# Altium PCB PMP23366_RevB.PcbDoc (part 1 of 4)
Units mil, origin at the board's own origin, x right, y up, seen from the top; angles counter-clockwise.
Board outline 6500 x 4250 mil, 4 copper layers (Top Layer 1, Inner Layer 2, Inner Layer 3, Bottom Layer 1), stack 75.824 mil thick; 370 components, 218 nets, 1221 pads, 351 vias.
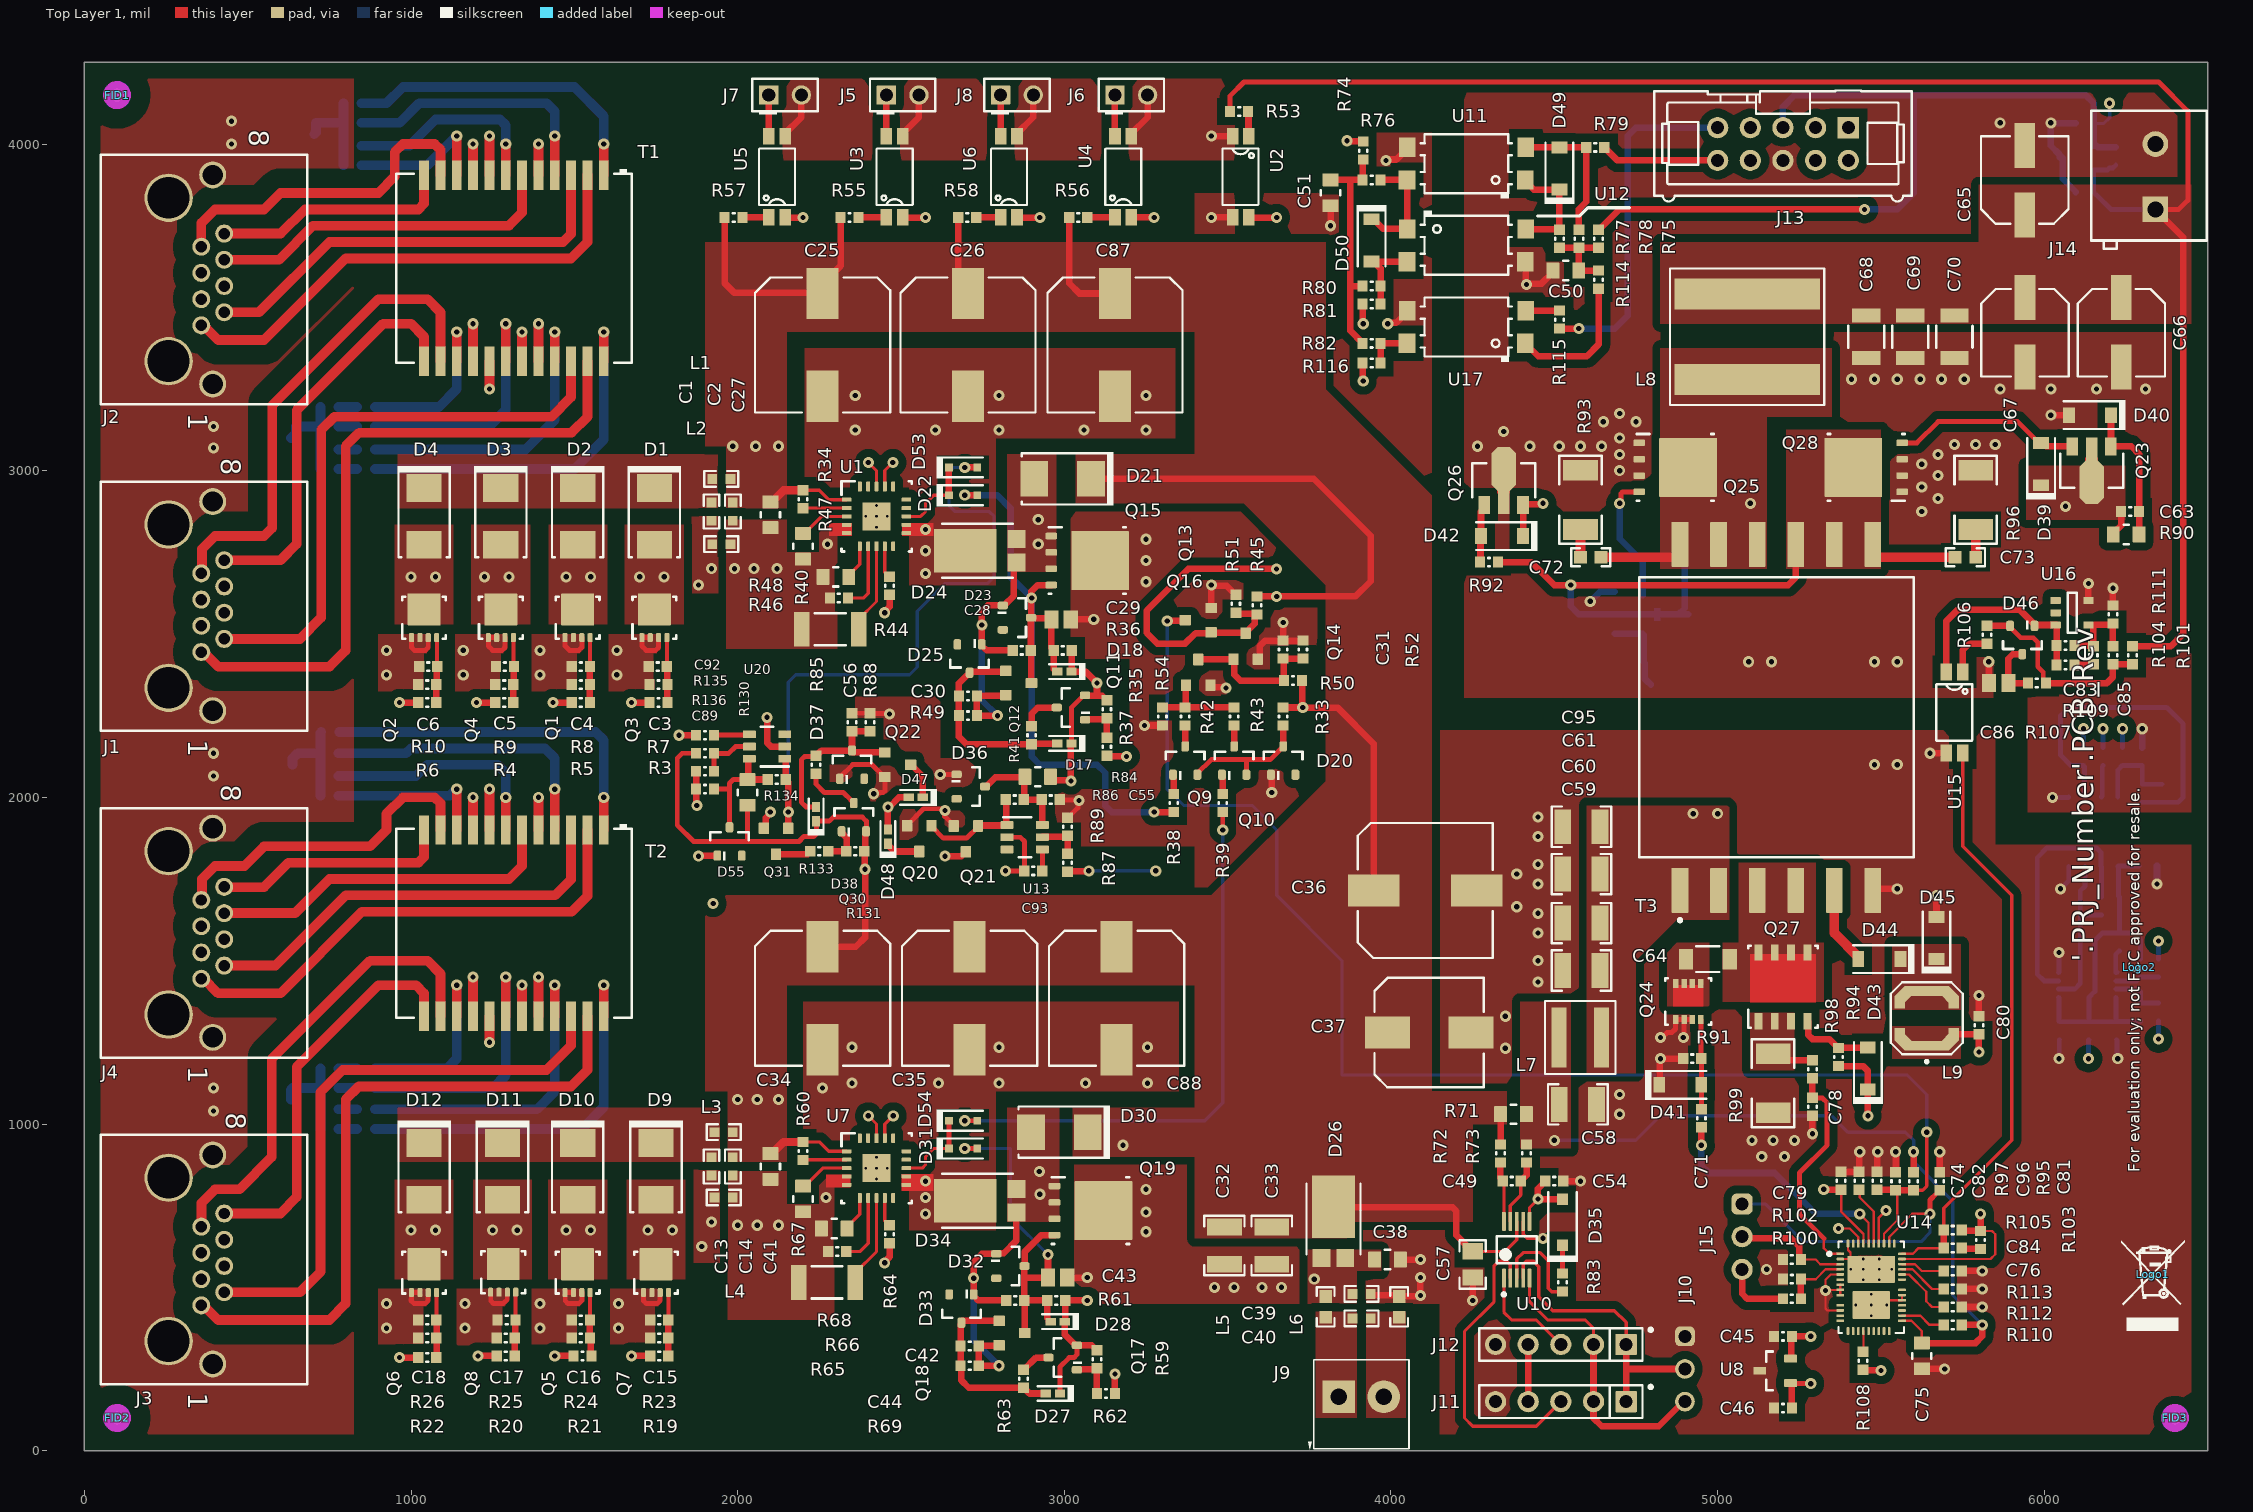
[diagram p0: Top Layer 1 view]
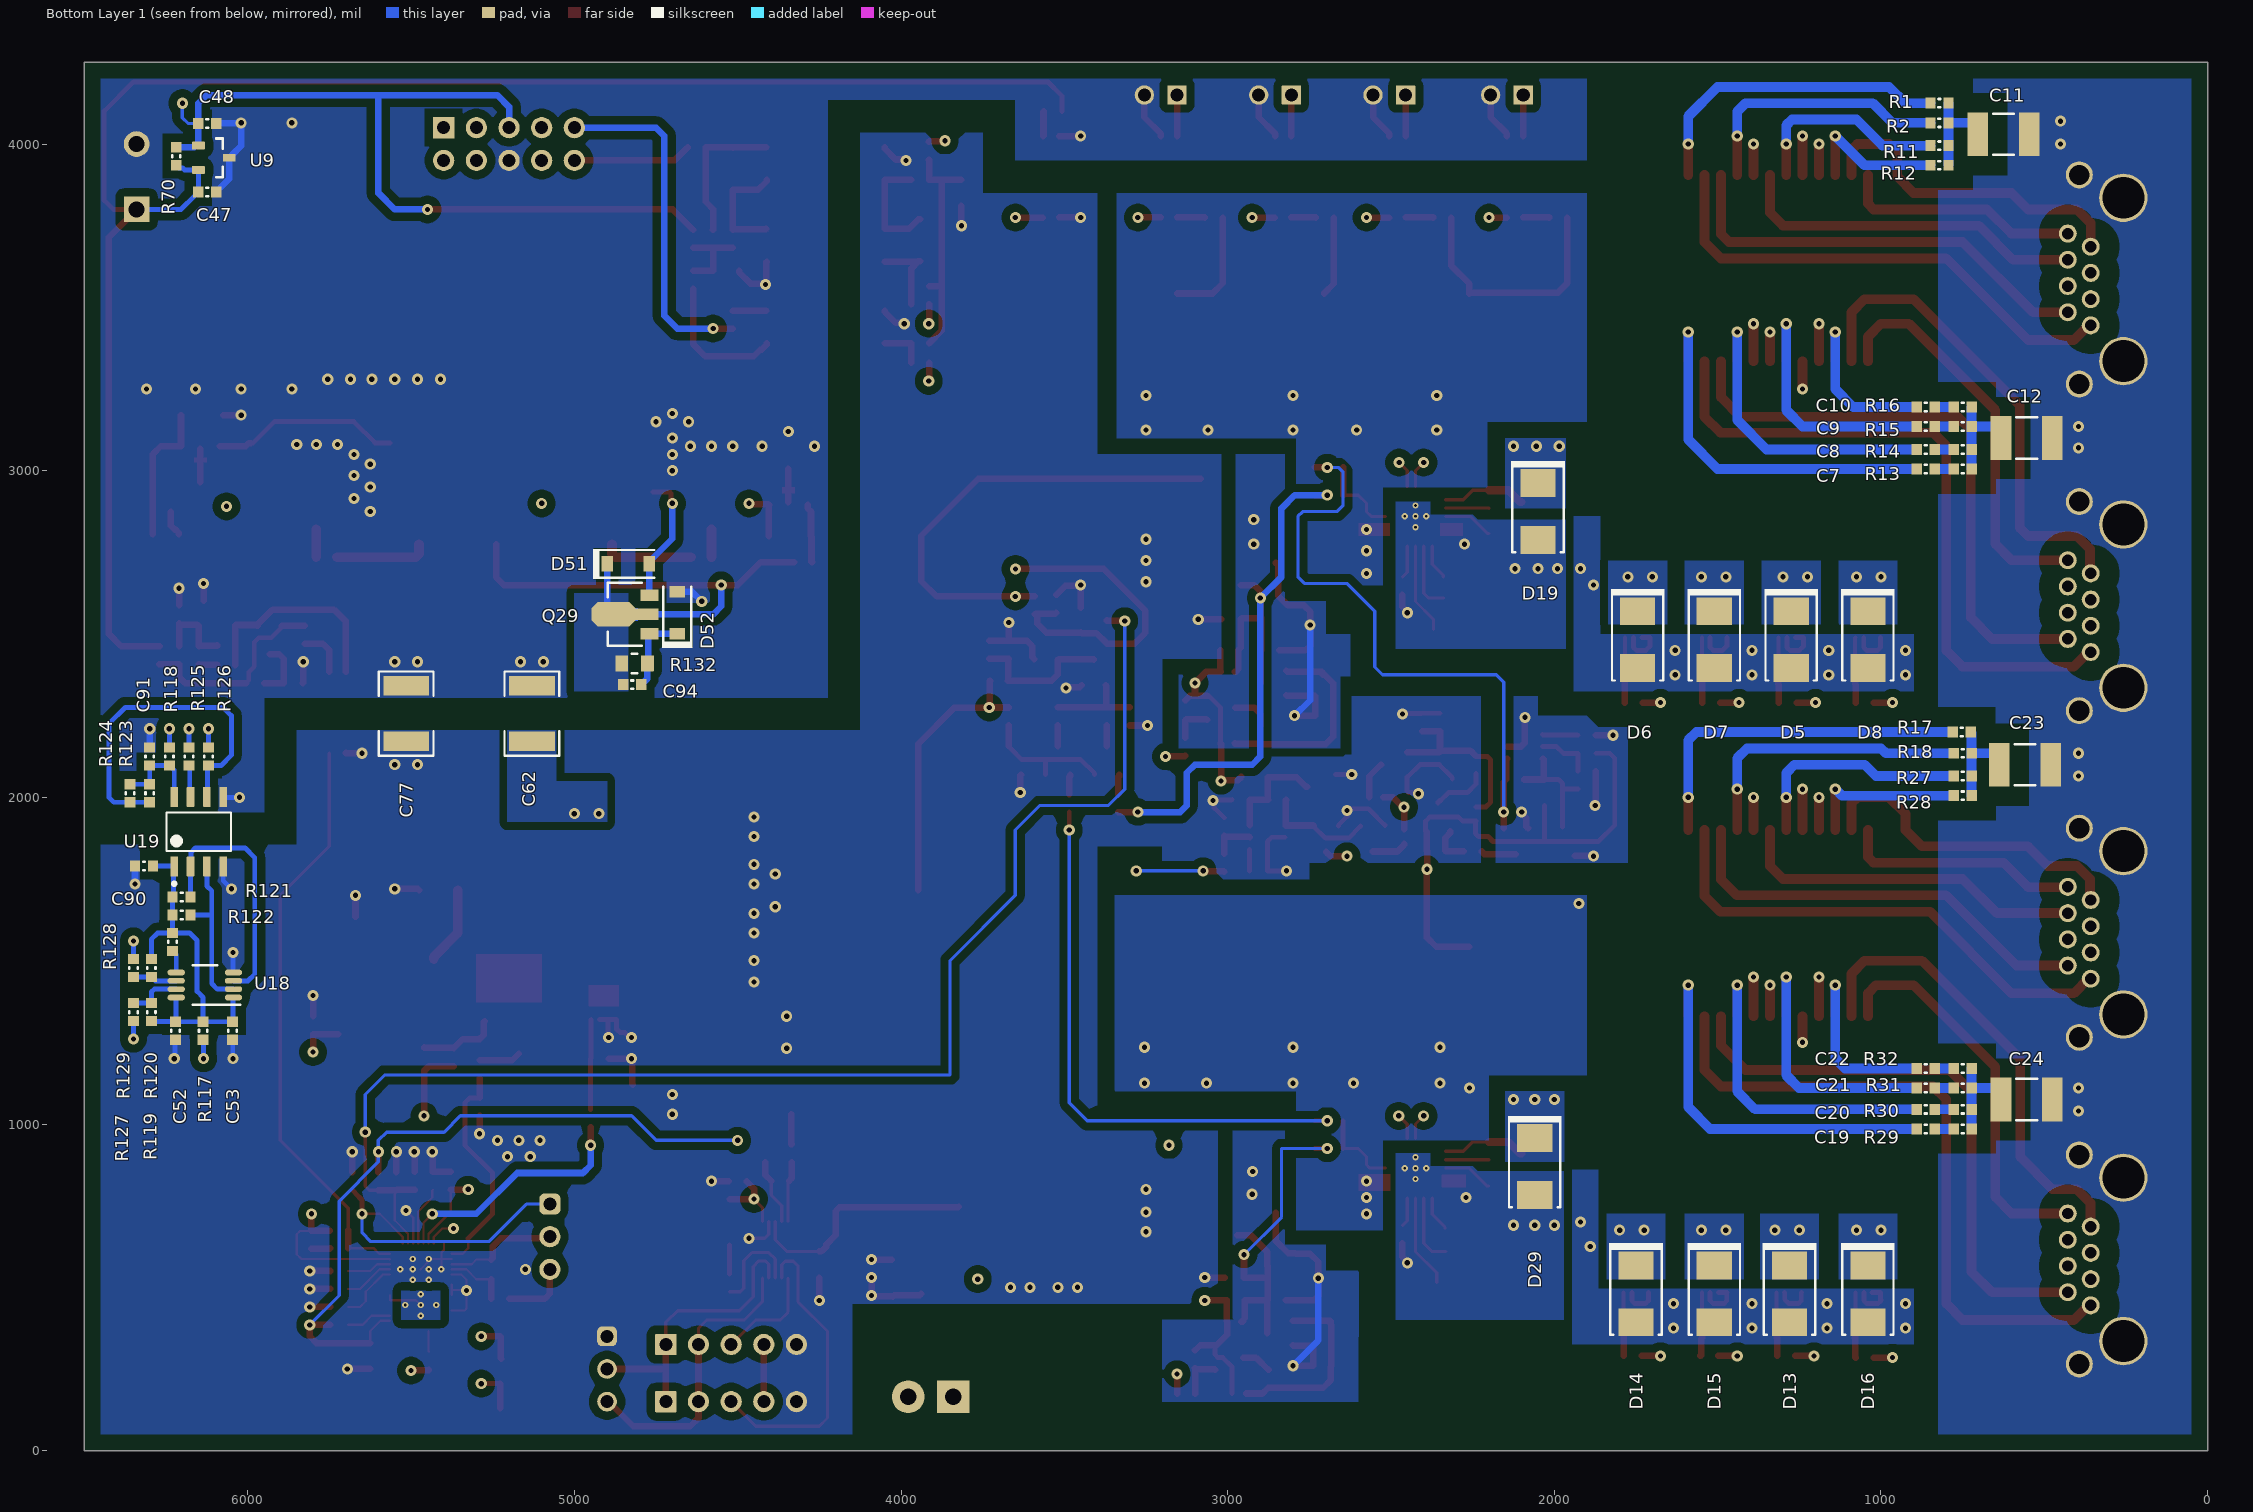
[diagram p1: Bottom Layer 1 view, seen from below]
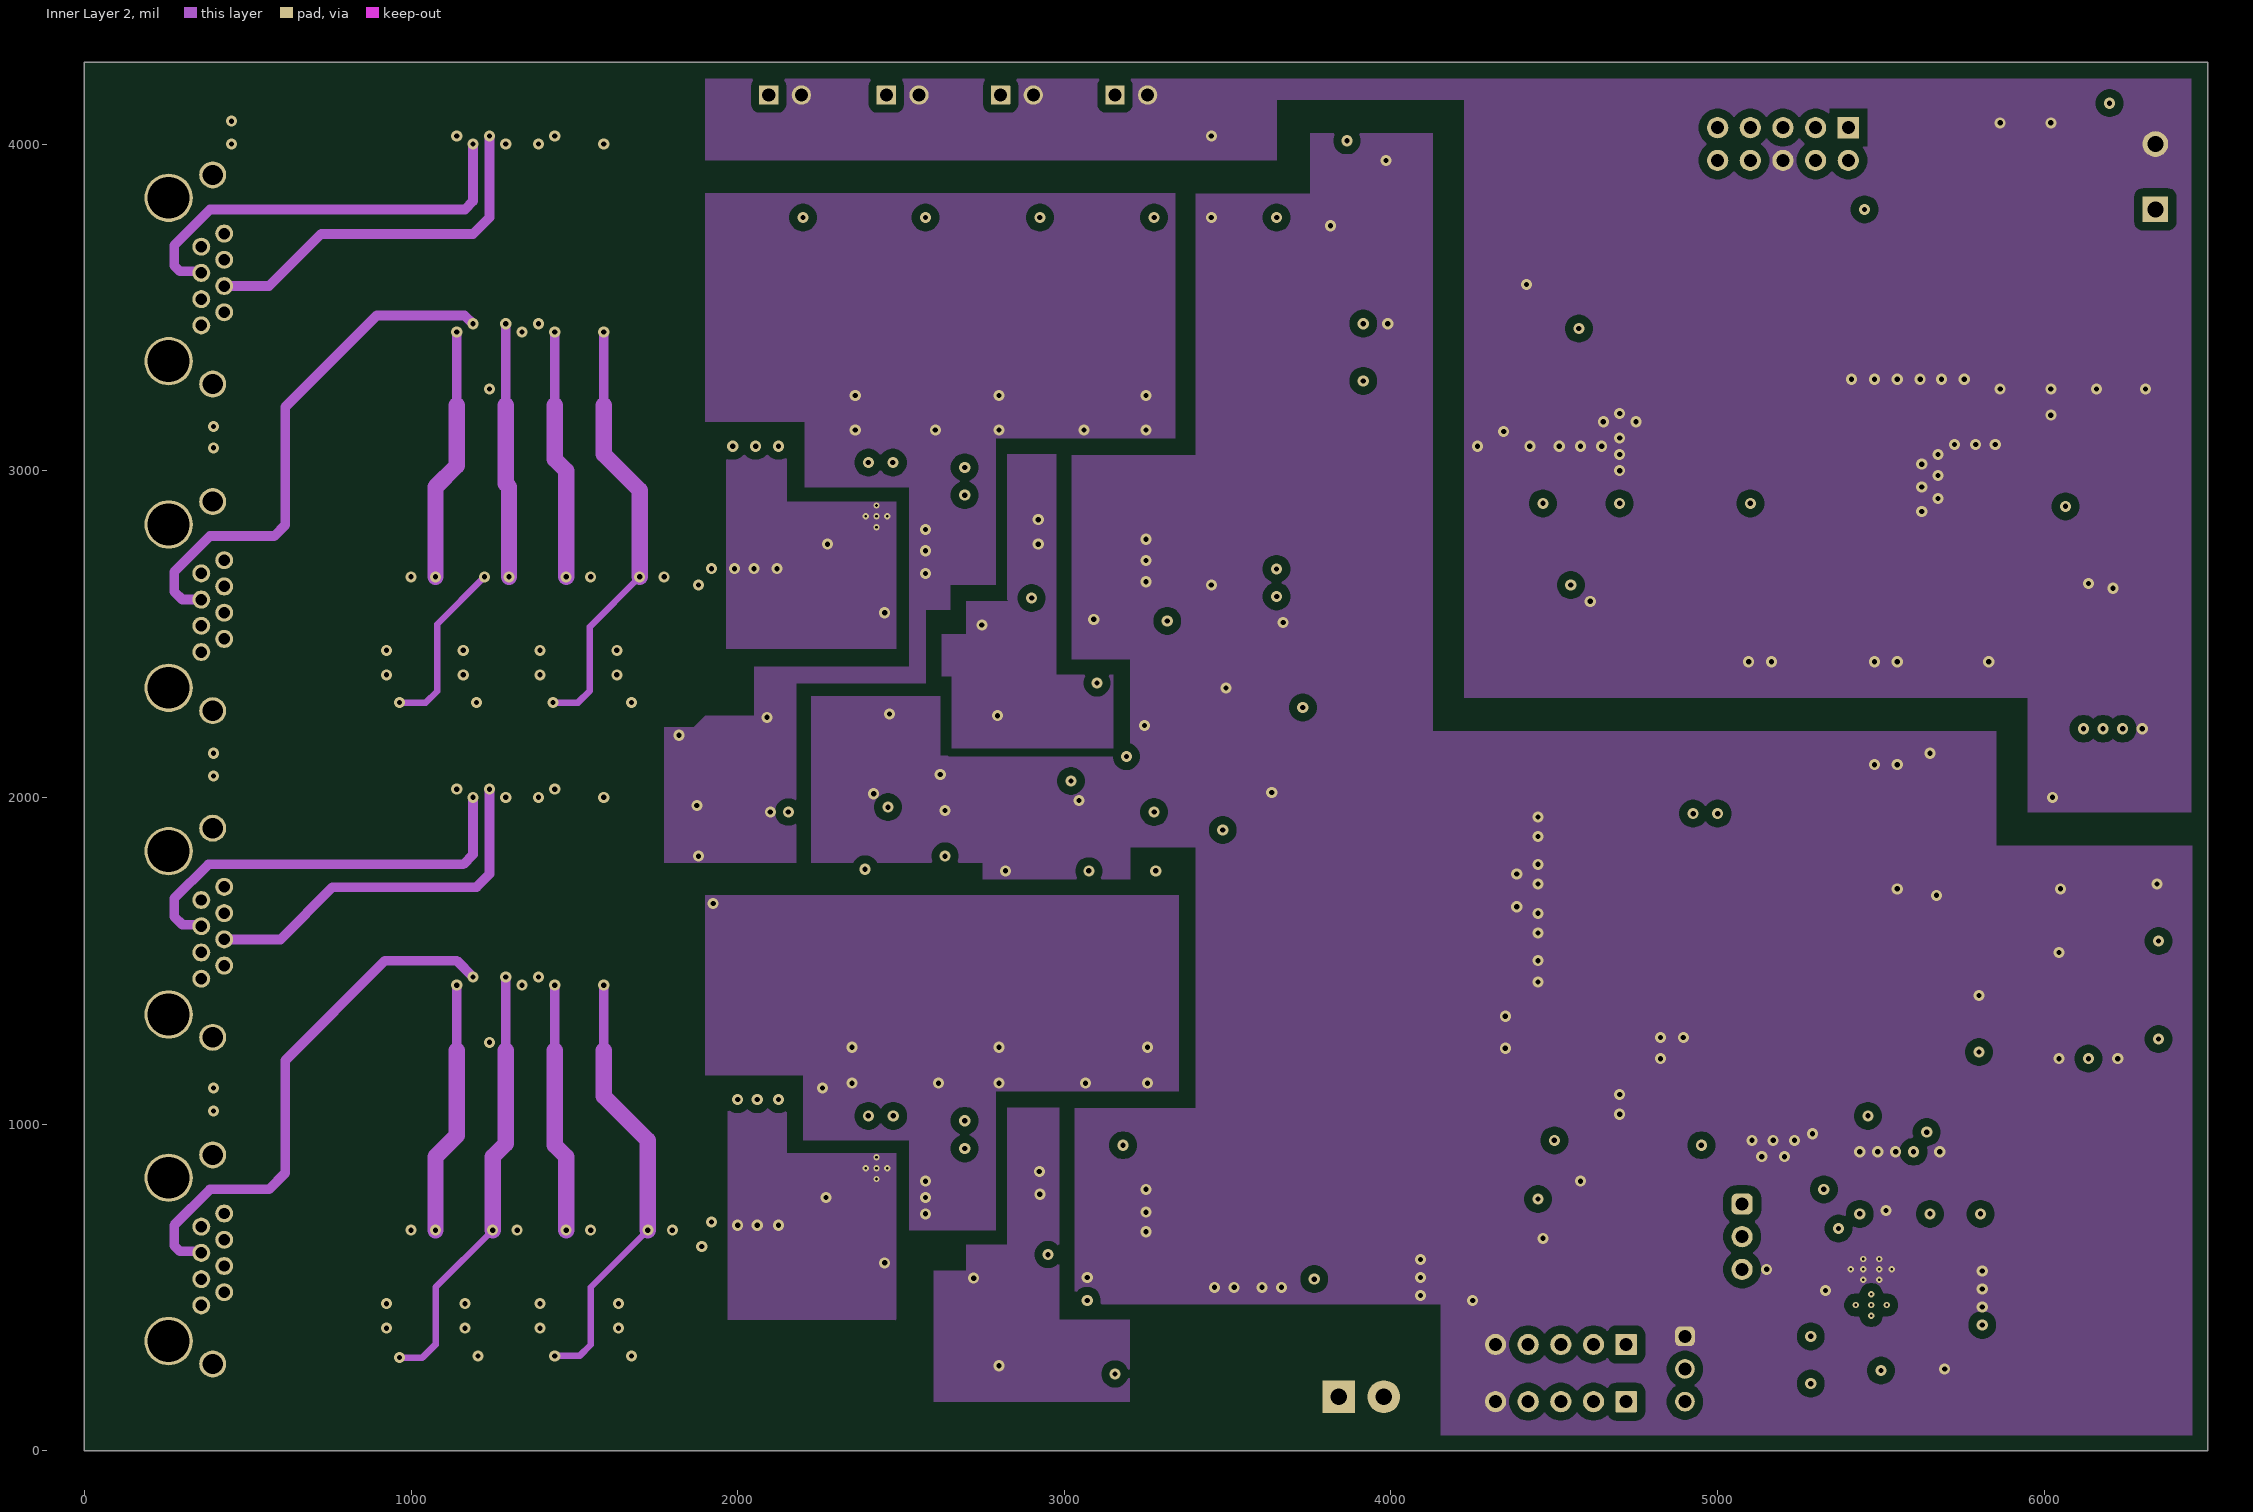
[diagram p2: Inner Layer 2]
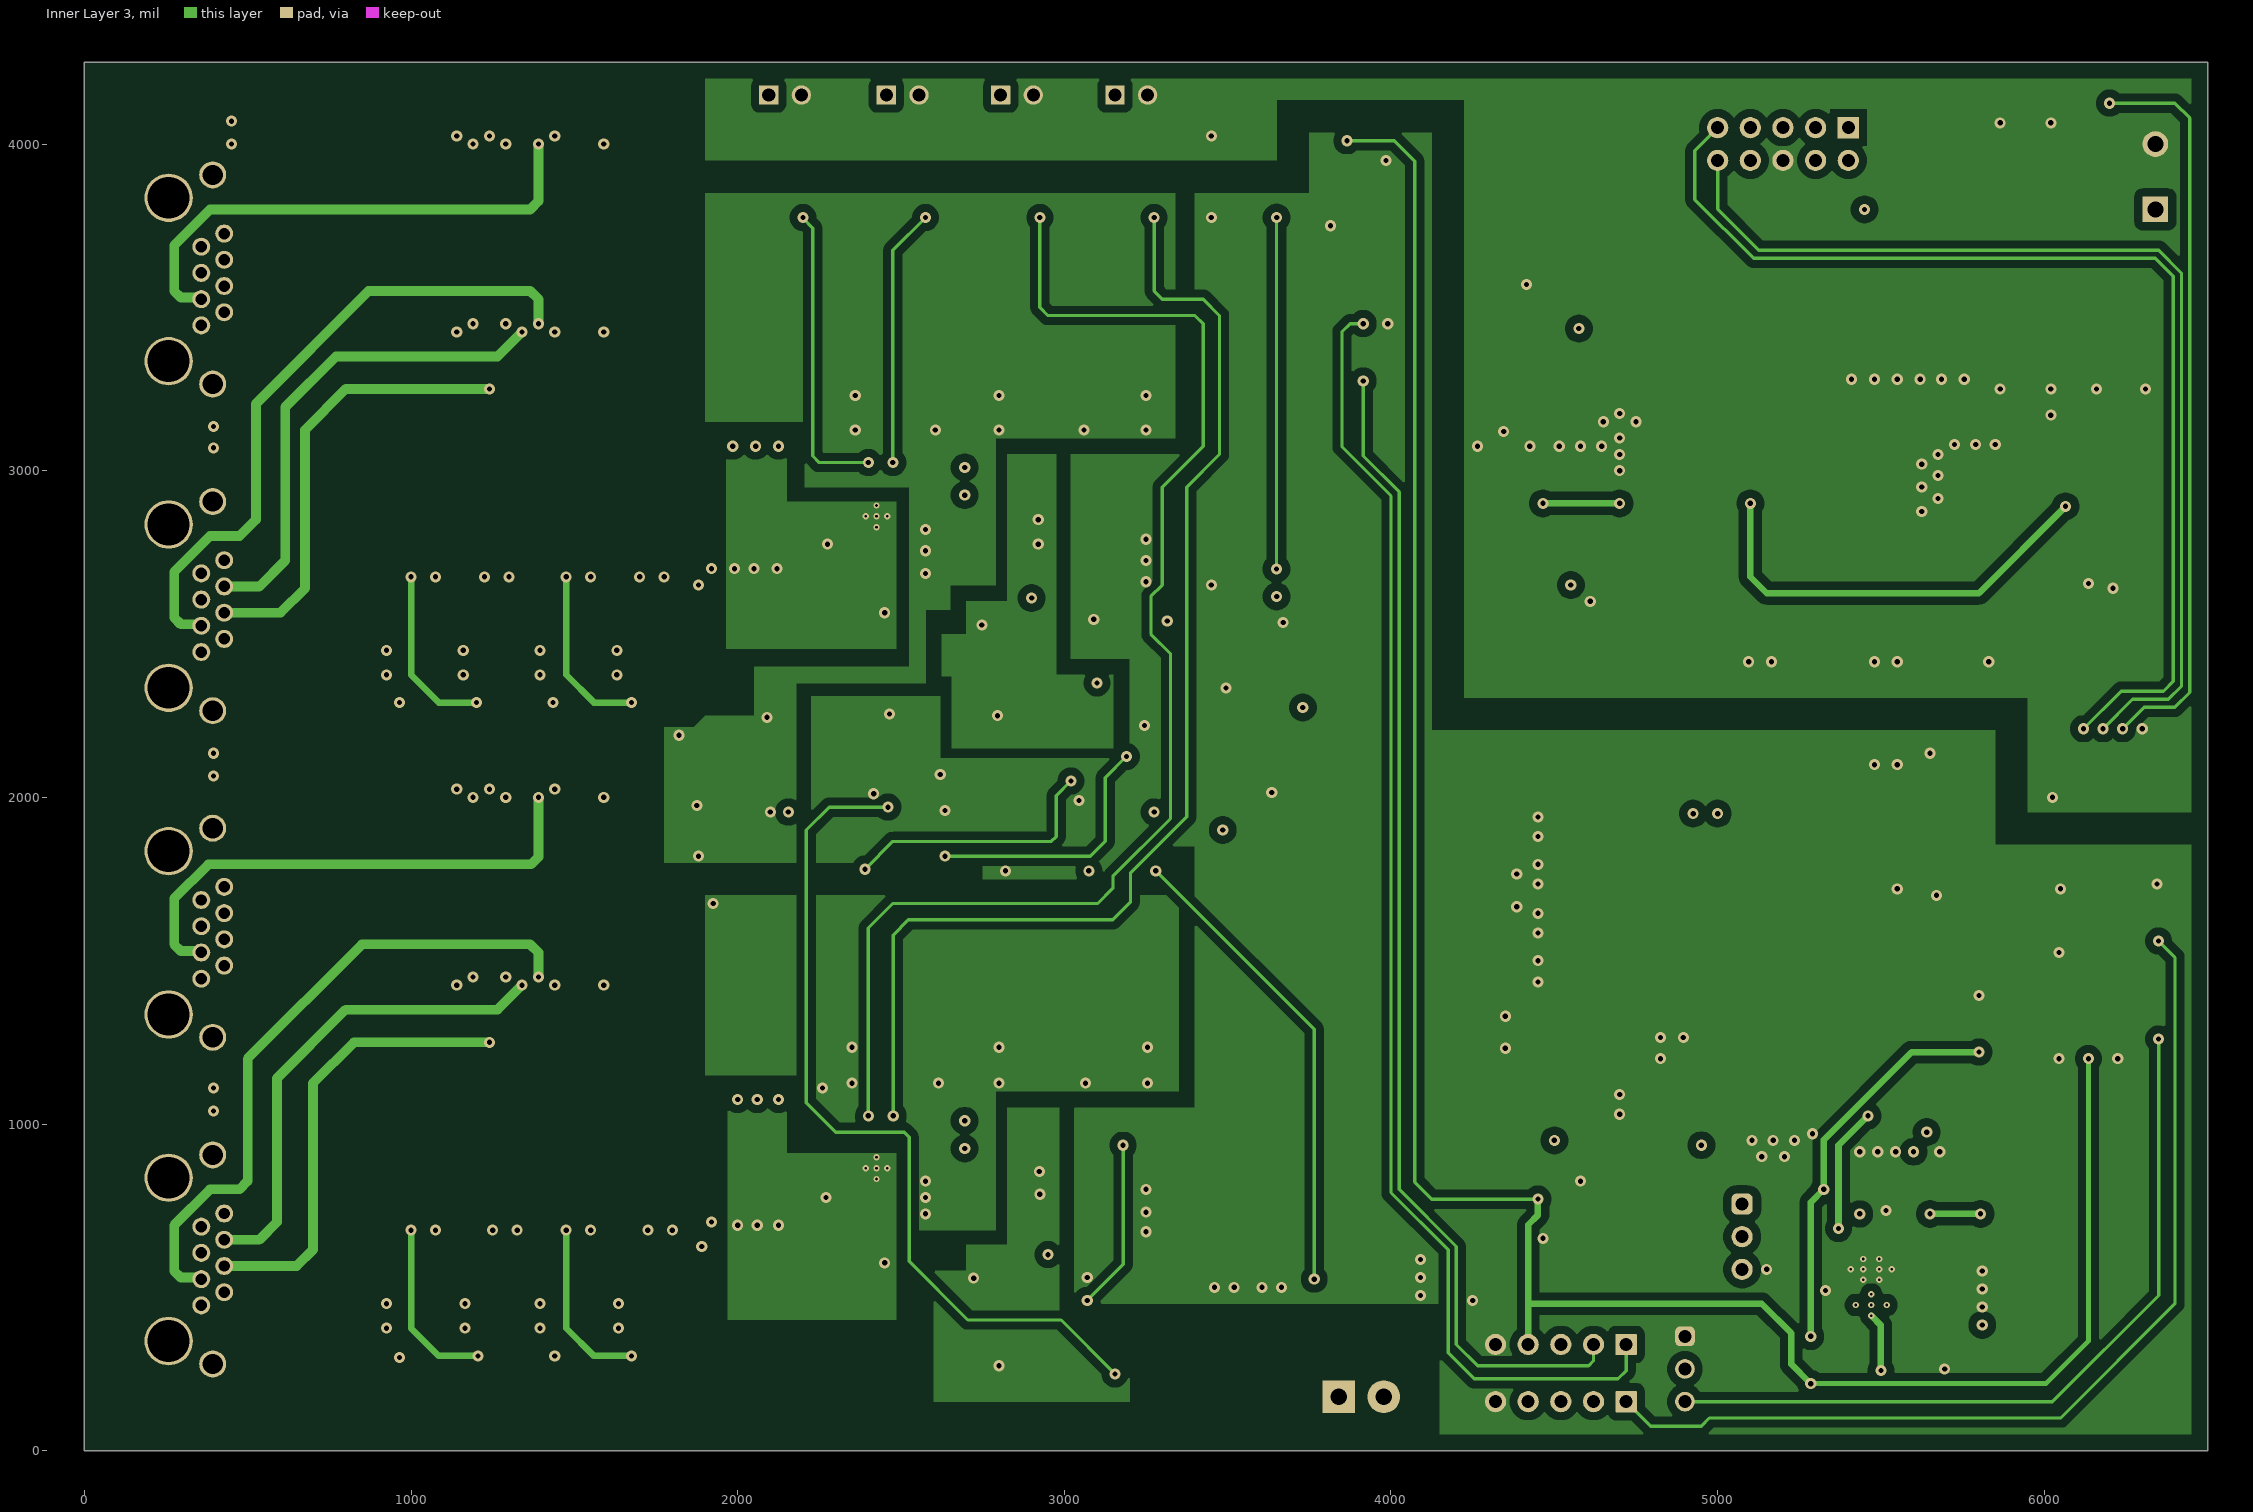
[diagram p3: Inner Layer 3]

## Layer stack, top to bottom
Top Solder: solder mask 0.4, Solder Resist, Dk 3.5
Top Layer 1: signal copper 2.7559
Core 1: core 2.8, PP-006, Dk 4.1
Inner Layer 2: signal copper 2.7559
Dielectric: prepreg 59.2, FR-4 High Tg, Dk 4.8
Inner Layer 3: signal copper 2.7559
Core 2: core 2.8, PP-006, Dk 4.1
Bottom Layer 1: signal copper 2.7559
Bottom Solder: solder mask 0.4, Solder Resist, Dk 3.5

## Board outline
0,0 0,4250 6500,4250 6500,0

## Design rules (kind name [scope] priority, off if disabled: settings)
AcuteAngle [All] p1: minimum=4.50000000000000E+0001 checktracksonly=FALSE
AssemblyTestPointUsage [All] p1: valid=2
BoardOutlineClearance BoardOutlineClearance_MountingHoles [OnCopper and InComponentClass('Mounting Holes')] p1: gap=39.37 ignorepadtopadclearanceinfootprint=FALSE
BoardOutlineClearance BoardOutlineClearance_Poly [OnCopper and IsPoly] p2: gap=25 ignorepadtopadclearanceinfootprint=FALSE
BoardOutlineClearance [OnCopper and Not InComponentClass('Logo') and not InComponentClass('FiducialMark') and not InRegion(1000,500,4000,800) and not InPoly] p3: gap=40 ignorepadtopadclearanceinfootprint=FALSE
Clearance Clearance_6 [InNamedPolygon('BOTTOM_LAYER_1_PGND_P077')] p1: gap=25 ignorepadtopadclearanceinfootprint=FALSE
Clearance Clearance_5 [InNamedPolygon('TOP_LAYER_1_PGND_P075')] p2: gap=25 ignorepadtopadclearanceinfootprint=FALSE
Clearance Clearance_4 [InNamedPolygon('BOTTOM_LAYER_1_GND_P074')] p3: gap=25 ignorepadtopadclearanceinfootprint=FALSE
Clearance Clearance_3 [InNamedPolygon('TOP_LAYER_1_GND_P072')] p4: gap=25 ignorepadtopadclearanceinfootprint=FALSE
Clearance Clearance_2 [InNamedPolygon('BOTTOM_LAYER_1_BSVG_P090')] p5: gap=60 ignorepadtopadclearanceinfootprint=FALSE
Clearance Clearance_1 [InNamedPolygon('TOP_LAYER_1_BSVG_P075')] p6: gap=60 ignorepadtopadclearanceinfootprint=FALSE
Clearance Clearance_Keepouts [((IsTrack Or IsArc) And Not InPoly) And IsFree and IsKeepOut vs ((IsTrack Or IsArc) And Not InPoly) And IsFree and IsKeepOut] p7: gap=0 ignorepadtopadclearanceinfootprint=FALSE
Clearance Clearance_Poly [InPolygon] p8: gap=25 ignorepadtopadclearanceinfootprint=TRUE
Clearance Clearance_FiducialMark [IsKeepOut and InComponentClass('FiducialMark') vs IsPad and InComponentClass('FiducialMark')] p9: gap=0 ignorepadtopadclearanceinfootprint=FALSE
Clearance [All] p10: gap=7.87 ignorepadtopadclearanceinfootprint=TRUE
ComponentClearance ComponentClearance_MountingHoles_FiducialMarks [InComponentClass('Mounting Holes') vs InComponentClass('FiducialMark')] p1: gap=50 collisioncheckmode=3 verticalgap=10 showdistances=FALSE
ComponentClearance ComponentClearance_Shunt [InComponentClass('Header') vs InComponentClass('Shunt')] p2: gap=0 collisioncheckmode=3 verticalgap=0 showdistances=FALSE
ComponentClearance ComponentClearance_Logo [InComponentClass('Logo')] p3: gap=30 collisioncheckmode=3 verticalgap=10 showdistances=FALSE
ComponentClearance ComponentClearance_ScrewToNut [(HasFootprint('NY PMS 440 0025 PH')) vs (HasFootprint('Keystone_1902C'))] p4: gap=5 collisioncheckmode=3 verticalgap=10 showdistances=FALSE
ComponentClearance ComponentClearance_MountingHoles [InComponentClass('Mounting Holes')] p5: gap=100 collisioncheckmode=3 verticalgap=100000 showdistances=FALSE
ComponentClearance ComponentClearance_SmallPassives [HasFootprint('0201*') or HasFootprint('0402*') or HasFootprint('0508') or HasFootprint('0603*') or HasFootprint('0612') or HasFootprint('0805*') or HasFootprint('0815*') or HasFootprint('0830*') or HasFootprint('1206*') or HasFootprint('1210*') or HasFootprint('1808*') or HasFootprint('1812*') or HasFootprint('1825*') or HasFootprint('2010*') or HasFootprint('2220*') or HasFootprint('2225*') or HasFootprint('2512*') or HasFootprint('2728*') or HasFootprint('3518*') vs HasFootprint('0201*') or HasFootprint('0402*') or HasFootprint('0508') or HasFootprint('0603*') or HasFootprint('0612') or HasFootprint('0805*') or HasFootprint('0815*') or HasFootprint('0830*') or HasFootprint('1206*') or HasFootprint('1210*') or HasFootprint('1808*') or HasFootprint('1812*') or HasFootprint('1825*') or HasFootprint('2010*') or HasFootprint('2220*') or HasFootprint('2225*') or HasFootprint('2512*') or HasFootprint('2728*') or HasFootprint('3518*')] p6: gap=14.96 collisioncheckmode=3 verticalgap=10 showdistances=FALSE
ComponentClearance ComponentClearance_THtoSMT [IsThruComponent vs IsSMTComponent] p7: gap=30 collisioncheckmode=3 verticalgap=30 showdistances=FALSE
ComponentClearance ComponentClearance_THtoTH [IsThruComponent vs IsThruComponent] p8: gap=20 collisioncheckmode=3 verticalgap=30 showdistances=FALSE
ComponentClearance [All] p9: gap=20 collisioncheckmode=3 verticalgap=10 showdistances=FALSE
DiffPairsRouting [All] p1: maxlimit=100 minlimit=10 mostfreqgap=10 toplayer_minwidth=15 toplayer_maxwidth=15 toplayer_prefwidth=15 midlayer1_minwidth=15 midlayer1_maxwidth=15 midlayer1_prefwidth=15 midlayer2_minwidth=15 midlayer2_maxwidth=15 midlayer2_prefwidth=15 bottomlayer_minwidth=15 bottomlayer_maxwidth=15 bottomlayer_prefwidth=15 maxuncoupledlength=1000
FabricationTestPointUsage TestPointUsage [All] p1: valid=2 allowmultiple=FALSE
FabricationTestpoint Testpoint [All] p1: side=3 testpointundercomponent=TRUE minsize=40 maxsize=100 preferedsize=60 minholesize=0 maxholesize=40 preferedholesize=32 testpointgrid=1 allowsidetop=TRUE allowsidebottom=TRUE usegrid=TRUE gridtolerance=0.01
FanoutControl Fanout_LCC [IsLCC] p1: bgadir=Out bgaviamode=Centered fanoutstyle=Auto fanoutdirection=Alternating viagrid=1 // Fanout_LCC (Default Rule)
FanoutControl Fanout_BGA [IsBGA] p2: bgadir=Out bgaviamode=Centered fanoutstyle=Auto fanoutdirection=Alternating viagrid=1 // Fanout_BGA (Default Rule)
FanoutControl Fanout_Default [All] p4: bgadir=Out bgaviamode=Centered fanoutstyle=Auto fanoutdirection=Alternating viagrid=1 // Fanout_Default (Default Rule)
FanoutControl Fanout_Small [(CompPinCount < 5)] p5: bgadir=Out bgaviamode=Centered fanoutstyle=Auto fanoutdirection=OutThenIn viagrid=1 // Fanout_Small (Default Rule)
HoleSize [All] p1: absolutevalues=TRUE maxlimit=251 minlimit=7.87 maxpercent=80.000 minpercent=20.000
MinimumAnnularRing MinimumAnnularRing_ThermalPadVias [IsVia and InAnyComponent] p1: minimumring=5.91
MinimumAnnularRing [All] p2: minimumring=7.87
MinimumSolderMaskSliver MinimumSolderMaskSliver_Logo [InComponentClass('Logo') vs InComponentClass('Logo')] p1: minsoldermaskwidth=0.7
MinimumSolderMaskSliver [All] p2: minsoldermaskwidth=3.94
PlaneConnect [All] p1: planeconnectstyle=Relief reliefexpansion=10 reliefentries=4 reliefconductorwidth=10 reliefairgap=10
PolygonConnect [All] p1: connectstyle=Direct reliefconductorwidth=10 reliefentries=4 polygonreliefangle="90 Angle" airgapwidth=10
RoutingVias ThermalPadVias [IsVia and InAnyComponent] p1: holewidth=7.87 width=19.68 viastyle="Through Hole" minholewidth=7.87 minwidth=19.68 maxholewidth=12.99 maxwidth=23.62
RoutingVias [All] p2: holewidth=16 width=34 viastyle="Through Hole" minholewidth=7.87 minwidth=24 maxholewidth=40 maxwidth=65
SilkToBoardRegionClearance [Not ((IsComment or IsDesignator) And (Hide <> 'False')) and not InRegion(1000,500,4000,800)] p1:
SilkToSilkClearance SilkToSilkClearance_Pb-FreeLogo [(HasFootprint('Pb-Free_Overlay_Medium') OR HasFootprint('Pb-Free_Overlay_Small')) vs (HasFootprint('Pb-Free_Overlay_Medium') OR HasFootprint('Pb-Free_Overlay_Small'))] p1: silktosilkclearance=0
SilkToSilkClearance [All] p2: silktosilkclearance=3.94
SilkToSolderMaskClearance SilkToComponentPadClearance [(IsPad or IsFill or IsRegion) and InAnycomponent] p1: minsilkscreentomaskgap=5 clearancetoexposedcopper=TRUE
SilkToSolderMaskClearance "Silk to Solder Mask Opening" [All] p2: minsilkscreentomaskgap=3.94 clearancetoexposedcopper=FALSE
SolderMaskExpansion [All] p1: expansion=1.97 istentingtop=FALSE
UnRoutedNet [All] p1: checkbadconnections=TRUE
Width [All] p1: maxlimit=100 minlimit=6 preferedwidth=10 checkconnectedcopper=TRUE
14 further rules are at their usual default settings.

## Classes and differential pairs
component class PMP23366_RevB_SH4: C58 C59 C60 C61 C62 C63 C64 C65 C66 C67 C68 C69 C70 C71 C72 C73 C74 C75 C76 C77 C78 C79 C80 C81 C82 C83 C84 C85 C86 C94 C95 C96 D39 D40 D41 D42 D43 D44 D45 D46 D51 D52 J14 J15 L7 L8 L9 Q23 Q24 Q25 Q26 Q27 Q28 Q29 R90 R91 R92 R93 R94 R95 R96 R97 R98 R99 R100 R101 R102 R103 R104 R105 R106 R107 R108 R109 R110 R111 R112 R113 R132 T3 U14 U15 U16
component class PMP23366_RevB_SH2: C25 C26 C27 C28 C29 C30 C31 C32 C33 C34 C35 C36 C37 C38 C39 C40 C41 C42 C43 C44 C87 C88 D17 D18 D19 D20 D21 D22 D23 D24 D25 D26 D27 D28 D29 D30 D31 D32 D33 D34 D53 D54 J5 J6 J7 J8 J9 L5 L6 Q9 Q10 Q11 Q12 Q13 Q14 Q15 Q16 Q17 Q18 Q19 R33 R34 R35 R36 R37 R38 R39 R40 R41 R42 R43 R44 R45 R46 R47 R48 R49 R50 R51 R52 R53 R54 R55 R56 R57 R58 R59 R60 R61 R62 R63 R64 R65 R66 R67 R68 R69 U1 U2 U3 U4 U5 U6 U7
component class PMP23366_RevB_SH1: C1 C2 C3 C4 C5 C6 C7 C8 C9 C10 C11 C12 C13 C14 C15 C16 C17 C18 C19 C20 C21 C22 C23 C24 D1 D2 D3 D4 D5 D6 D7 D8 D9 D10 D11 D12 D13 D14 D15 D16 FID1 FID2 FID3 J1 J2 J3 J4 L1 L2 L3 L4 Logo1 Logo2 Q1 Q2 Q3 Q4 Q5 Q6 Q7 Q8 R1 R2 R3 R4 R5 R6 R7 R8 R9 R10 R11 R12 R13 R14 R15 R16 R17 R18 R19 R20 R21 R22 R23 R24 R25 R26 R27 R28 R29 R30 R31 R32 T1 T2
component class Header: J5 J6 J7 J8 J10 J11 J12 J15
component class PMP23366_RevB_SH3: C45 C46 C47 C48 C49 C50 C51 C52 C53 C54 C55 C56 C57 C89 C90 C91 C92 C93 D35 D36 D37 D38 D47 D48 D49 D50 D55 J10 J11 J12 J13 Q20 Q21 Q22 Q30 Q31 R70 R71 R72 R73 R74 R75 R76 R77 R78 R79 R80 R81 R82 R83 R84 R85 R86 R87 R88 R89 R114 R115 R116 R117 R118 R119 R120 R121 R122 R123 R124 R125 R126 R127 R128 R129 R130 R131 R133 R134 R135 R136 U8 U9 U10 U11 U12 U13 U17 U18 U19 U20
component class FiducialMark: FID1 FID2 FID3

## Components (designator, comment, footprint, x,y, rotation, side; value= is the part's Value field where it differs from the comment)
C1 "Capacitor" 0603_HV 1920,2875 r270 top value=1000pF
C2 "Capacitor" 0603_HV 1985,2875 r270 top value=1000pF
C3 "Capacitor" 0603L 1755,2400 r180 top value=330pF
C4 "Capacitor" 0603L 1520,2400 r180 top value=330pF
C5 "Capacitor" 0603L 1287.44,2400 r180 top value=330pF
C6 "Capacitor" 0603L 1052.44,2400 r180 top value=330pF
C7 "Capacitor" 0603L 862.56,3005 r180 bottom value=0.01uF
C8 "Capacitor" 0603L 862.56,3065 r180 bottom value=0.01uF
C9 "Capacitor" 0603L 862.56,3135 r180 bottom value=0.01uF
C10 "Capacitor" 0603L 862.56,3195 r180 bottom value=0.01uF
C11 "Capacitor" 1812 624.8,4030 r0 bottom value=1000pF
C12 "Capacitor" 1812 553.74,3100 r180 bottom value=1000pF
C13 "Capacitor" 0603_HV 1920,870 r270 top value=1000pF
C14 "Capacitor" 0603_HV 1985,870 r270 top value=1000pF
C15 "Capacitor" 0603L 1760,400 r180 top value=330pF
C16 "Capacitor" 0603L 1520,400 r180 top value=330pF
C17 "Capacitor" 0603L 1292.44,400 r180 top value=330pF
C18 "Capacitor" 0603L 1050,400 r180 top value=330pF
C19 "Capacitor" 0603L 862.56,985 r180 bottom value=0.01uF
C20 "Capacitor" 0603L 862.56,1045 r180 bottom value=0.01uF
C21 "Capacitor" 0603L 862.56,1110 r180 bottom value=0.01uF
C22 "Capacitor" 0603L 862.56,1170 r180 bottom value=0.01uF
C23 "Capacitor" 1812 558.74,2100 r0 bottom value=1000pF
C24 "Capacitor" 1812 553.74,1075 r180 bottom value=1000pF
C25 "EEHZC1K470P" SM_RADIAL_10BMM 2260,3385 r270 top value=47uF
C26 "EEHZC1K470P" SM_RADIAL_10BMM 2705,3385 r270 top value=47uF
C27 "Capacitor" 0805_HV1 2100,2865 r90 top value=0.1uF
C28 "Capacitor" 0603L 2870,2450 r180 top value=1000pF
C29 "Capacitor" 0805L 2990,2545 r180 top value=0.047uF
C30 "Capacitor" 0603L 2705,2310 r0 top value=1000pF
C31 "Capacitor" 0603L 3670,2452.56 r90 top value=0.01uF
C32 "Capacitor" 1210_270 3490,627.91 r90 top value=2.2uF
C33 "Capacitor" 1210_270 3635,627.91 r90 top value=2.2uF
C34 "EEHZC1K470P" SM_RADIAL_10BMM 2260,1385 r270 top value=47uF
C35 "EEHZC1K470P" SM_RADIAL_10BMM 2710,1385 r270 top value=47uF
C36 "EEHZC1K470P" SM_RADIAL_10BMM 4105,1715 r0 top value=47uF
C37 "EEHZC1K220P" SM_RADIAL_8MM 4117.05,1280 r0 top value=22uF
C38 "Capacitor" 0805_HV1 3989.37,585 r0 top value=0.1uF
C39 "Capacitor" 0603_HV 3910,480 r0 top value=1000pF
C40 "Capacitor" 0603_HV 3910,405 r0 top value=1000pF
C41 "Capacitor" 0805_HV1 2100,870 r90 top value=0.1uF
C42 "Capacitor" 0603L 2850,460 r180 top value=1000pF
C43 "Capacitor" 0805L 2979.53,530 r180 top value=0.047uF
C44 "Capacitor" 0603L 2710,320 r0 top value=1000pF
C45 "885012206095" 0603L 5200,350 r180 top value=0.1uF
C46 "885012206095" 0603L 5200,130 r180 top value=0.1uF
C47 "885012206095" 0603L 6123.74,3853 r180 bottom value=0.1uF
C48 "885012206095" 0603L 6123.74,4063 r180 bottom value=0.1uF
C49 "885012206095" 0603L 4370,825 r180 top value=0.1uF
C50 "TMK212B7105KG-T" 0805_HV1 4535.26,3612.56 r0 top value=1uF
C51 "TMK212B7105KG-T" 0805_HV1 3815,3850.63 r90 top value=1uF
C52 "885012206095" 0603L 6221.3,1285.55 r90 bottom value=0.1uF
C53 "885012206095" 0603L 6046.3,1285.55 r270 bottom value=0.1uF
C54 "885012206095" 0603L 4500,825 r0 top value=0.1uF
C55 "Capacitor" 0603L 2958.52,1992.95 r180 top value=0.01uF
C56 "Capacitor" 0603L 2350,2230 r90 top value=1000pF
C57 "Capacitor" 0805_HV 4250,570 r90 top value=0.1uF
C58 "Capacitor" 1210_270 4572.09,1060 r0 top value=2.2uF
C59 "Capacitor" 1210_270 4582.91,1470 r180 top value=2.2uF
C60 "Capacitor" 1210_270 4582.91,1615 r180 top value=2.2uF
C61 "Capacitor" 1210_270 4582.91,1765 r180 top value=2.2uF
C62 "Capacitor" 1812_HV 5130,2256.26 r90 bottom value=4700pF
C63 "885012206081" 0603L 6262.56,2875 r180 top value=470pF
C64 "GRM31CR72E473KW03L" 1206_180 4970,1505 r0 top value=0.047uF
C65 "10SVPE220M" CAPSMT_62_F61 5940.97,3887.73 r90 top value=220uF
C66 "10SVPE220M" CAPSMT_62_F61 6235,3425 r270 top value=220uF
C67 "10SVPE220M" CAPSMT_62_F61 5940,3425 r270 top value=220uF
C68 "C1210C107M8PACTU" 1210_280 5455,3410 r90 top value=100uF
C69 "C1210C107M8PACTU" 1210_280 5590,3410 r90 top value=100uF
C70 "C1210C107M8PACTU" 1210_280 5725,3410 r90 top value=100uF
C71 "885012206095" 0603L 4950,1017.44 r90 top value=0.1uF
C72 "885012206087" 0603 4611.5,2735 r0 top value=4700pF
C73 "Capacitor" 0603 5758.5,2735 r0 top value=1000pF
C74 "885012206095" 0603L 5378,826.26 r270 top value=0.1uF
C75 "Capacitor" 0805_HV1 5625,290 r270 top value=0.1uF
C76 "Capacitor" 0603L 5720,550 r0 top value=0.047uF
C77 "Capacitor" 1812_HV 5515,2256.26 r90 bottom value=4700pF
C78 "GRM1885C1H470JA01D" 0603L 5290,1052.44 r90 top value=47pF
C79 "C0603C222K5RAC" 0603L 5227.44,585 r180 top value=2200pF
C80 "885012206095" 0603L 5800,1302.56 r270 top value=0.1uF
C81 "885012206095" 0603L 5680,825 r270 top value=0.1uF
C82 "885012206095" 0603L 5433,826.26 r270 top value=0.1uF
C83 "885012006057" 0603L 6065,2465 r180 top value=100pF
C84 "Capacitor" 0603L 5720,620 r180 top value=0.047uF
C85 "GRM188R71H333KA61D" 0603L 6150,2435 r270 top value=0.033uF
C86 "TMK212B7105KG-T" 0805L 5860.47,2350 r0 top value=1uF
C87 "EEHZC1K470P" SM_RADIAL_10BMM 3155,3385 r270 top value=47uF
C88 "EEHZC1K470P" SM_RADIAL_10BMM 3160,1385 r270 top value=47uF
C89 "Capacitor" 0603L 1900,2025 r0 top value=0.01uF
C90 "885012206095" 0603L 6317.56,1790 r180 bottom value=0.1uF
C91 "885012206095" 0603L 6300,2125 r270 bottom value=0.1uF
C92 "885012006057" 0603L 1900,2190 r180 top value=100pF
C93 "885012006057" 0603L 2905,1775 r180 top value=100pF
C94 "885012206081" 0603L 4822.44,2345 r0 bottom value=470pF
C95 "Capacitor" 1210_270 4582.91,1910 r180 top value=2.2uF
C96 "Capacitor" 0603L 5545,825 r90 top value=1000pF
D1 "B2100-13-F" SMB 1745,2860 r270 top value=100V
D2 "B2100-13-F" SMB 1510,2860 r270 top value=100V
D3 "B2100-13-F" SMB 1275,2860 r270 top value=100V
D4 "B2100-13-F" SMB 1040,2860 r270 top value=100V
D5 "B2100-13-F" SMB 1275,2482.99 r270 bottom value=100V
D6 "B2100-13-F" SMB 1745,2482.99 r270 bottom value=100V
D7 "B2100-13-F" SMB 1510,2482.99 r270 bottom value=100V
D8 "B2100-13-F" SMB 1040,2482.99 r270 bottom value=100V
D9 "B2100-13-F" SMB 1750,855 r270 top value=100V
D10 "B2100-13-F" SMB 1510,855 r270 top value=100V
D11 "B2100-13-F" SMB 1280,855 r270 top value=100V
D12 "B2100-13-F" SMB 1040,855 r270 top value=100V
D13 "B2100-13-F" SMB 1280,480 r270 bottom value=100V
D14 "B2100-13-F" SMB 1750,480 r270 bottom value=100V
D15 "B2100-13-F" SMB 1510,480 r270 bottom value=100V
D16 "B2100-13-F" SMB 1040,480 r270 bottom value=100V
D17 "BAS516,115" SOD-523 3000,2165 r180 top value=100V
D18 "BAS516,115" SOD-523 3000,2385 r180 top value=100V
D19 "SMBJ58A-13-F" SMB 2050,2875 r270 bottom value=58V
D20 "MMBZ5231BLT1G" SOT-23L 3670,2112.56 r90 top value=5.1V
D21 "SMBJ58A-13-F" SMB 2995,2975 r180 top value=58V
D22 "BAT46WJ,115" SOD-323F 2690,2925 r0 top value=100V
D23 "MMBZ5240BLT1G" SOT-23L 2855,2550 r0 top value=10V
D24 "PDS3100-13" POWERDI5 2775,2755 r180 top value=100V
D25 "MMBZ5240BLT1G" SOT-23L 2710,2425 r270 top value=10V
D26 "PDS3100-13" POWERDI5 3823.78,668.39 r90 top value=100V
D27 "BAS516,115" SOD-523 2965,175 r180 top value=100V
D28 "BAS516,115" SOD-523 2980,395 r180 top value=100V
D29 "SMBJ58A-13-F" SMB 2060,870 r270 bottom value=58V
D30 "SMBJ58A-13-F" SMB 2985,975 r180 top value=58V
D31 "BAT46WJ,115" SOD-323F 2690,925 r0 top value=100V
D32 "MMBZ5240BLT1G" SOT-23L 2835,565 r0 top value=10V
D33 "MMBZ5240BLT1G" SOT-23L 2685,435 r270 top value=10V
D34 "PDS3100-13" POWERDI5 2775,765 r180 top value=100V
D35 "HLMP-Q150-F0011" HLMP-Q150_Red 4525,700.08 r90 top value=Red
D36 "MMBZ5231BLT1G" SOT-23L 2713.52,2032.95 r0 top value=5.1V
D37 "BAS516,115" SOD-523 2240,1948.82 r90 top value=100V
D38 "MMBZ5240BLT1G" SOT-23L 2350,2100 r90 top value=10V
D39 "DIODE" SOD-123 5990,3020 r90 top value=100V
D40 "Zener" SOD-123 6140,3170 r180 top value=10V
D41 "DIODE" SOD-123 4885.53,1120 r0 top value=100V
D42 "DIODE" SOD-123 4340,2800 r180 top value=100V
D43 "DIODE" SOD-123 5460,1170 r90 top value=100V
D44 "DIODE" SOD-123 5495,1505 r180 top value=100V
D45 "DIODE" SOD-123 5670,1569.47 r90 top value=100V
D46 "BAT54S-7-F" SOT-23L 5932.6,2481.69 r270 top value=30V
D47 "BAS516,115" SOD-523 2545,2000 r180 top value=100V
D48 "BAS516,115" SOD-523 2460,1880 r90 top value=100V
D49 "MBR0520LT1G" SOD-123 4515.61,3925 r90 top value=20V
D50 "MBR0520LT1G" SOD-123 3940.61,3705 r270 top value=20V
D51 "DIODE" SOD-123 4835,2715 r180 bottom value=100V
D52 "Zener" SOD-123 4685,2565 r90 bottom value=10V
D53 "BAT46WJ,115" SOD-323F 2690,3010 r0 top value=100V
D54 "BAT46WJ,115" SOD-323F 2690,1010 r0 top value=100V
D55 "MMBZ5231BLT1G" SOT-23L 1975,1865 r90 top value=5.1V
FID1 "Fiducial" Fiducial10-20 100,4150 r0 top
FID2 "Fiducial" Fiducial10-20 100,100 r0 top
FID3 "Fiducial" Fiducial10-20 6400,100 r0 top
J1 "1-406541-1" TEC_1-406541-1 365,2585 r270 top
J2 "1-406541-1" TEC_1-406541-1 365,3585 r270 top
J3 "1-406541-1" TEC_1-406541-1 365,585 r270 top
J4 "1-406541-1" TEC_1-406541-1 365,1585 r270 top
J5 "PEC02SAAN" CONN_PEC02SAAN 2505,4150 r0 top
J6 "PEC02SAAN" CONN_PEC02SAAN 3205,4150 r0 top
J7 "PEC02SAAN" CONN_PEC02SAAN 2145,4150 r0 top
J8 "PEC02SAAN" CONN_PEC02SAAN 2855,4150 r0 top
J9 "ED555/2DS" TERM_BLK_ED555-2DS 3840,165 r0 top
J10 "TSW-103-08-G-S" Samtec_TSW-103-08-x-S 4900,250 r270 top
J11 "HTSW-105-07-G-S" Samtec_HTSW-105-07-G-S 4520,150 r180 top
J12 "HTSW-105-07-G-S" Samtec_HTSW-105-07-G-S 4520,325 r180 top
J13 "N2510-6002-RB" CONN_2510-6002 5200,4000 r180 top
J14 "Receptacle_2x1" On-Shore_ED120_2DS 6340,3900 r90 top
J15 "TSW-103-07-G-S" TSW-103-07-G-S 5075,655 r270 top
L1 "Ferrite_Bead" 0603_HV 1950,2975 r0 top value="220 ohm"
L2 "Ferrite_Bead" 0603_HV 1950,2775 r0 top value="220 ohm"
L3 "Ferrite_Bead" 0603_HV 1957,975 r0 top value="220 ohm"
L4 "Ferrite_Bead" 0603_HV 1957,775 r0 top value="220 ohm"
L5 "Ferrite_Bead" 0603 3800,440 r90 top value="220 ohm"
L6 "Ferrite_Bead" 0603 4025,440 r90 top value="220 ohm"
L7 "Inductor_Iron" XAL5030 4580,1265 r0 top value=3.3uH
L8 "XAL1010-332MEB" XAL1010 5090,3410 r90 top value=3.3uH
L9 "Inductor_Iron" LPS5030 5640,1323.66 r90 top value=2.2mH
Logo1 "WEEE logo" WEEE_Minimum 6331.3,539.37 r0 top
Logo2 "FCC disclaimer" FCC_disclaimer 6290,1480 r90 top
Q1 "CSD19538Q3A" DNH0008A_NV 1510,2550 r90 top value=100V
Q2 "CSD19538Q3A" DNH0008A_NV 1040,2550 r90 top value=100V
Q3 "CSD19538Q3A" DNH0008A_NV 1745,2550 r90 top value=100V
Q4 "CSD19538Q3A" DNH0008A_NV 1275,2550 r90 top value=100V
Q5 "CSD19538Q3A" DNH0008A_NV 1510,545 r90 top value=100V
Q6 "CSD19538Q3A" DNH0008A_NV 1040,545 r90 top value=100V
Q7 "CSD19538Q3A" DNH0008A_NV 1750,545 r90 top value=100V
Q8 "CSD19538Q3A" DNH0008A_NV 1282.2,546.02 r90 top value=100V
Q9 "BSS63" SOT-23L 3370,2112.56 r90 top value="100 V"
Q10 "BSS63" SOT-23L 3520,2112.56 r90 top value="100 V"
Q11 "BSS63" SOT-23L 3020,2275 r180 top value="100 V"
Q12 "BSS123-7-F" FP-BSS123-7-F_SOT23-MFG 2860,2350 r0 top
Q13 "BSS123-7-F" FP-BSS123-7-F_SOT23-MFG 3410,2542.56 r180 top
Q14 "BSS123-7-F" FP-BSS123-7-F_SOT23-MFG 3555,2462.56 r90 top
Q15 "CSD19534Q5A" DQJ0008A 3070,2725 r0 top value=100V
Q16 "BSS123-7-F" FP-BSS123-7-F_SOT23-MFG 3410,2382.56 r90 top
Q17 "BSS63" SOT-23L 2995,285 r180 top value="100 V"
Q18 "BSS123-7-F" FP-BSS123-7-F_SOT23-MFG 2840,360 r0 top
Q19 "CSD19534Q5A" DQJ0008A 3080,735 r0 top value=100V
Q20 "BSS123-7-F" FP-BSS123-7-F_SOT23-MFG 2556.12,1873.58 r270 top
Q21 "BSS123-7-F" FP-BSS123-7-F_SOT23-MFG 2698.52,1872.95 r270 top
Q22 "BSS123-7-F" FP-BSS123-7-F_SOT23-MFG 2490,2100 r0 top
Q23 "FCX491TA" SOT-89-3 6145,3000 r270 top value="60 V"
Q24 "MOSFET_P_D5678G4S123" MLP08S 4910,1375 r90 top value=-150V
Q25 "CSD17578Q5A" DQJ0008A 4870.04,3010 r0 top value=30V
Q26 "DXT2907A-13" SOT-89-3 4345,2970 r90 top value="60 V"
Q27 "FDMS86250" TRANS_Fairchild_PQFN08A 5200,1420 r90 top value=150V
Q28 "CSD17578Q5A" DQJ0008A 5454.96,3010 r180 top value=30V
Q29 "FCX491TA" SOT-89-3 4845,2560 r0 bottom value="60 V"
Q30 "BSS63" SOT-23L 2355.53,1939.25 r90 top value="100 V"
Q31 "BSS123-7-F" FP-BSS123-7-F_SOT23-MFG 2117.6,1865.63 r270 top
R1 "Resistor" 0603L 821.06,4125 r0 bottom value=75.0
R2 "Resistor" 0603L 821.06,4065 r0 bottom value=75.0
R3 "Resistor" 0603L 1757.44,2290 r0 top value=1.00Meg
R4 "Resistor" 0603L 1285,2290 r0 top value=1.00Meg
R5 "Resistor" 0603L 1520,2290 r0 top value=1.00Meg
R6 "Resistor" 0603L 1050,2290 r0 top value=1.00Meg
R7 "Resistor" 0603L 1757.44,2345 r0 top value=232k
R8 "Resistor" 0603L 1520,2345 r0 top value=232k
R9 "Resistor" 0603L 1285,2345 r0 top value=232k
R10 "Resistor" 0603L 1050,2345 r0 top value=232k
R11 "Resistor" 0603L 821.06,3995 r0 bottom value=75.0
R12 "Resistor" 0603L 821.06,3935 r0 bottom value=75.0
R13 "Resistor" 0603L 750,3005 r0 bottom value=75.0
R14 "Resistor" 0603L 750,3065 r0 bottom value=75.0
R15 "Resistor" 0603L 750,3135 r0 bottom value=75.0
R16 "Resistor" 0603L 750,3195 r0 bottom value=75.0
R17 "Resistor" 0603L 752.44,2200 r0 bottom value=75.0
R18 "Resistor" 0603L 750,2135 r0 bottom value=75.0
R19 "Resistor" 0603L 1760,290 r0 top value=1.00Meg
R20 "Resistor" 0603L 1290,290 r0 top value=1.00Meg
R21 "Resistor" 0603L 1525,290 r0 top value=1.00Meg
R22 "Resistor" 0603L 1050,285 r0 top value=1.00Meg
R23 "Resistor" 0603L 1760,345 r0 top value=232k
R24 "Resistor" 0603L 1520,345 r0 top value=232k
R25 "Resistor" 0603L 1290,345 r0 top value=232k
R26 "Resistor" 0603L 1050,345 r0 top value=232k
R27 "Resistor" 0603L 750,2065 r0 bottom value=75.0
R28 "Resistor" 0603L 750,2005 r0 bottom value=75.0
R29 "Resistor" 0603L 750,985 r0 bottom value=75.0
R30 "Resistor" 0603L 750,1045 r0 bottom value=75.0
R31 "Resistor" 0603L 750,1110 r0 bottom value=75.0
R32 "Resistor" 0603L 750,1170 r0 bottom value=75.0
R33 "Resistor" 0603L 3670,2247.56 r90 top value=20.0k
R34 "Resistor" 0603L 2200,2912.44 r90 top value=27.4k
R35 "Resistor" 0603L 3130,2270 r90 top value=10.0k
R36 "Resistor" 0603L 2995,2450 r0 top value=100k
R37 "Resistor" 0603L 3130,2155 r270 top value=137k
R38 "Resistor" 0603L 3335,1982.56 r90 top value=100k
R39 "Resistor" 0603L 3485,1982.56 r90 top value=100k
R40 "CRCW060360K4FKEA" 0603L 2465,2647.44 r270 top value=60.4k
R41 "Resistor" 0603L 2900,2190 r90 top value=100k
R42 "Resistor" 0603L 3370,2247.56 r90 top value=1.78k
R43 "Resistor" 0603L 3520,2247.56 r270 top value=1.78k
R44 "CRCW20101K30JNEF" 2010L 2283.39,2515 r180 top value=1.3k
R45 "Resistor" 0603L 3590,2587.56 r90 top value=44.2k
R46 "Resistor" 0603L 2310,2610 r0 top value=49.9k
R47 "Resistor" 0805_HV1 2200,2768.7 r90 top value=63.4
R48 "CRCW0805249RFKEA" 0805_HV1 2300.63,2675 r0 top value=249
R49 "Resistor" 0603L 2705,2250 r180 top value=30.1k
R50 "Resistor" 0603L 3700,2357.56 r180 top value=44.2k
R51 "Resistor" 0603L 3525,2592.56 r270 top value=10.0k
R52 "Resistor" 0603L 3730,2452.56 r270 top value=10.0k
R53 "Resistor" 0603L 3535,4100 r180 top value=1.00k
R54 "Resistor" 0603L 3300,2247.56 r90 top value=10.0k
R55 "RC0603FR-0735K7L" 0603L 2342.44,3775 r0 top value=35.7k
R56 "RC0603FR-0735K7L" 0603L 3042.44,3775 r0 top value=35.7k
R57 "RC0603FR-0735K7L" 0603L 1987.44,3775 r0 top value=35.7k
R58 "RC0603FR-0735K7L" 0603L 2702.44,3775 r0 top value=35.7k
R59 "CRCW060310K0FKEA" 0603L 3100,280 r90 top value=10.0k
R60 "Resistor" 0603L 2200,917.44 r90 top value=27.4k
R61 "Resistor" 0603L 2975,460 r0 top value=100k
R62 "Resistor" 0603L 3127.44,175 r0 top value=137k
R63 "Resistor" 0603L 2875,220 r90 top value=100k
R64 "CRCW060360K4FKEA" 0603L 2465,662.44 r270 top value=60.4k
R65 "CRCW20101K30JNEF" 2010L 2273.39,515 r180 top value=1.3k
R66 "Resistor" 0603L 2305,610 r0 top value=49.9k
R67 "Resistor" 0805_HV1 2200,770.63 r90 top value=63.4
R68 "CRCW0805249RFKEA" 0805_HV1 2295.63,680 r0 top value=249
R69 "Resistor" 0603L 2710,260 r180 top value=30.1k
R70 "CRCW06030000Z0EA" 0603L 6218.74,3963 r90 bottom value=0
R71 "RL0805FR-070R025L" 0805_HV1 4375,1030 r0 top value=0.1
R72 "CRCW060320R0JNEA" 0603L 4335,910 r270 top value=20
R73 "CRCW060320R0JNEA" 0603L 4415,910 r270 top value=20
R74 "CRCW06030000Z0EA" 0603L 3915,3980 r270 top value=0
R75 "CRCW06030000Z0EA" 0603L 4635.61,3710 r270 top value=0
R76 "Resistor" 0603L 3940.61,3890 r0 top value=1.00k
R77 "Resistor" 0603L 4515.61,3710 r270 top value=1.00k
R78 "Resistor" 0603L 4575.61,3710 r270 top value=10.0k
R79 "CRCW06030000Z0EA" 0603L 4625.61,3990 r0 top value=0
R80 "CRCW060315K0FKEA" 0603L 3940.61,3565 r0 top value=15.0k
R81 "CRCW06030000Z0EA" 0603L 3940.61,3510 r180 top value=0
R82 "CRCW06034K99FKEA" 0603L 3940.61,3390 r0 top value=4.99k
R83 "CRCW06034K70JNEA" 0603L 4525,515 r270 top value=4.7k
R84 "CRCW080539K0JNEA" 0805_HV1 2918.52,2062.95 r180 top value=39k
R85 "Resistor" 0603L 2240,2100 r270 top value=100k
R86 "Resistor" 0603L 2848.52,1992.95 r180 top value=20.0k
R87 "Resistor" 0603L 3010,1800 r270 top value=100k
R88 "Resistor" 0603L 2405,2230 r270 top value=30.1k
R89 "Resistor" 0603L 3010,1910 r270 top value=1.02k
R90 "CRCW0805499RFKEA" 0805_HV1 6250.63,2805 r0 top value=499
R91 "Resistor" 0603L 4922.44,1200 r0 top value=10.0k
R92 "Resistor" 0603L 4300,2720 r0 top value=10
R93 "CRCW20105R10JNEF" 2010 4580,2910.55 r90 top value=5.1
R94 "CRCW060310R0JNEA" 0603L 5370,1205 r90 top value=10
R95 "CRCW060393K1FKEA" 0603L 5600,825 r270 top value=93.1k
R96 "CRCW20105R10JNEF" 2010 5790,2910.55 r90 top value=5.1
R97 "Resistor" 0603L 5488,826.26 r270 top value=10.0k
R98 "Resistor" 0603L 5290,1167.44 r90 top value=1.00k
R99 "MCR50JZHFSR068" 2010 5170,1124.45 r270 top value=0.068
R100 "CRCW0603237KFKEA" 0603L 5227.44,465 r0 top value=237k
R101 "Resistor" 0603L 6270,2435 r270 top value=0
R102 "CRCW060360K4FKEA" 0603L 5227.44,525 r180 top value=60.4k
R103 "Resistor" 0603L 5805,645 r90 top value=2.00k
R104 "Resistor" 0603L 6210,2435 r90 top value=10.0k
R105 "Resistor" 0603L 5720,675 r0 top value=2.00k
R106 "Resistor" 0603L 5825,2497.44 r90 top value=665
R107 "Resistor" 0603L 5977.44,2350 r180 top value=10.0k
R108 "CRCW060349K9FKEA" 0603L 5445.06,274.86 r90 top value=49.9k
R109 "CRCW06034K99FKEA" 0603L 6065,2405 r0 top value=4.99k
R110 "CRCW060349K9FKEA" 0603L 5720,385 r180 top value=49.9k
R111 "Resistor" 0603L 6210,2560 r270 top value=3.24k
R112 "CRCW060324K9FKEA" 0603L 5720,440 r180 top value=24.9k
R113 "CRCW0603499KFKEA" 0603L 5720,495 r180 top value=499k
R114 "Resistor" 0603L 4635.61,3585 r90 top value=1.00k
R115 "CRCW06030000Z0EA" 0603L 4515.61,3462.56 r270 top value=0
R116 "CRCW06030000Z0EA" 0603L 3940.61,3330 r180 top value=0
R117 "CRCW06030000Z0EA" 0603L 6136.3,1285.55 r270 bottom value=0
R118 "CRCW06030000Z0EA" 0603L 6240,2125 r90 bottom value=0
R119 "CRCW06034K70JNEA" 0603L 6295,1342.56 r90 bottom value=4.7k
R120 "CRCW06034K70JNEA" 0603L 6295,1477.56 r90 bottom value=4.7k
R121 "CRCW06034K70JNEA" 0603L 6202.44,1695 r0 bottom value=4.7k
R122 "CRCW06034K70JNEA" 0603L 6202.44,1640 r0 bottom value=4.7k
R123 "CRCW06034K70JNEA" 0603L 6300,2012.44 r90 bottom value=4.7k
R124 "CRCW06034K70JNEA" 0603L 6360,2012.44 r90 bottom value=4.7k
R125 "CRCW06030000Z0EA" 0603L 6180,2125 r90 bottom value=0
R126 "CRCW06030000Z0EA" 0603L 6120,2125 r90 bottom value=0
R127 "CRCW06030000Z0EA" 0603L 6350,1342.56 r90 bottom value=0
R128 "CRCW06034K70JNEA" 0603L 6230,1557.44 r270 bottom value=4.7k
R129 "CRCW06030000Z0EA" 0603L 6350,1477.56 r270 bottom value=0
R130 "CRCW080539K0JNEA" 0805_HV1 2030,2015 r90 top value=39k
R131 "Resistor" 0603L 2360,1835 r0 top value=10.0k
R132 "CRCW0805499RFKEA" 0805_HV1 4815.71,2410 r180 bottom value=499
R133 "Resistor" 0603L 2250,1835 r180 top value=137k
R134 "Resistor" 0603L 2120,2055 r0 top value=20.0k
R135 "Resistor" 0603L 1900,2135 r180 top value=100k
R136 "Resistor" 0603L 1900,2080 r0 top value=1.02k
T1 "7490220122" Wurth_7490220122 1315,3619.96 r270 top value=350uH
T2 "7490220122" Wurth_7490220122 1315,1615 r270 top value=350uH
T3 "LDT8618-50" FP-LDT8618-50_SMT_XFRFMR_21MM5_21MM1-MFG 5180,2245 r0 top
U1 "TPS2372-3RGWR" RGW0020B 2425,2860 r0 top
U2 "TCMT1107" SOP-4 3540,3900 r270 top
U3 "TCMT1107" SOP-4 2480,3900 r90 top
U4 "TCMT1107" SOP-4 3180,3900 r90 top
U5 "TCMT1107" SOP-4 2120,3900 r90 top
U6 "TCMT1107" SOP-4 2830,3900 r90 top
U7 "TPS2372-3RGWR" RGW0020B 2425,865 r0 top
U8 "TLV76050DBZR" DBZ0003A_N 5176.06,244.42 r180 top
U9 "TLV76050DBZR" DBZ0003A_N 6103.74,3958 r180 bottom
U10 "INA237AQDGSRQ1" DGS0010A-MFG 4385,615 r90 top
U11 "FOD817DS" N04C 4230.61,3940 r180 top
U12 "FOD817DS" N04C 4230.61,3690 r0 top
U13 "TPS3808G01DBVR" DBV0006A_N 2878.52,1877.95 r0 top
U14 "TPS23734RMT" RMT0045A-MFG 5470,500 r0 top
U15 "TCMT1107" SOP-4 5725,2260 r270 top
U16 "TLV431AIDBVR" DBV0005A_L 6085,2565 r0 top
U17 "FOD817DS" N04C 4230.61,3440 r180 top
U18 "TCA9517ADGKR" DGK0008A_N 6131.3,1425.55 r0 bottom
U19 "ISO1640BDR" D0008A-MFG 6150,1895 r90 bottom
U20 "TPS3808G01DBVR" DBV0006A_N 2090,2155.55 r180 top

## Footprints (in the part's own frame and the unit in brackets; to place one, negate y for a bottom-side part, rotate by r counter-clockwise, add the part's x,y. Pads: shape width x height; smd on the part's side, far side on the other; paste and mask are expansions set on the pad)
0603 [mm] "0603 from SM-752 data"
  rect 1x0.95 smd: 1(-0.8,0) 2(0.8,0)
  silkscreen extent -1.52,-0.69 1.52,0.69, body extent -0.87,-0.47 0.87,0.47, height 1
0603_HV [mil] "Ernesto recommended land pattern.  26 mil between pads."
  rect 30x30 smd: 1(-28,0) 2(28,0)
  silkscreen extent -52,-24 52,24, body extent -34,-19 34,19, height 39
0603L [mm] "0603 from SM-752 data"
  rect 0.8x0.85 smd: 1(-0.7,0) 2(0.7,0)
  silkscreen extent -0.07,-0.33 0.07,0.33, body extent -0.87,-0.47 0.87,0.47, height 1
0805_HV [mil] "0805 with 30mil clearance between pads"
  rect 50x63 smd: 1(-40,0) 2(40,0)
  silkscreen extent -74,-40 74,40, body extent -43,-29 43,29, height 57
0805_HV1 [mm] "Custom footprint based on analyzing multiple manufacturer recommendations"
  rrect10% 1x1.25 smd: 1(-1,0) 2(1,0)
  silkscreen extent -0.2,-0.75 0.2,0.75, body extent -1.1,-0.72 1.1,0.73, height 1.45
0805L [mm] "0805 from SM-752 data"
  rect 1.1x1.4 smd: 1(-0.75,0) 2(0.75,0)
  body extent -1.1,-0.72 1.1,0.72, height 1.45
1206_180 [mm] "1206_180"
  rect 1.1x1.6 smd: 1(-1.7,0) 2(1.7,0)
  silkscreen extent -0.9,-1 0.9,1, body extent -1.75,-0.95 1.75,0.95, height 1.8
1210_270 [mm] "1210"
  rect 1.3x2.7 smd: 1(-1.45,0) 2(1.45,0)
  silkscreen extent -2.32,-1.57 2.32,1.57, body extent -1.7,-1.35 1.7,1.35, height 2.7
1210_280 [mm] "SMD, 2-Leads, Body 3.6x2.8mm, Height 2.8mm"
  rect 1.1x2.2 smd: 1(-1.65,0) 2(1.65,0)
  silkscreen extent -0.84,-1.4 0.84,1.4, body extent -1.8,-1.4 1.8,1.4, height 2.8
1812 [mm]
  rect 1.6x3.4 smd: 1(-2,0) 2(2,0)
  silkscreen extent -0.8,-1.6 0.8,1.6, body extent -2.4,-1.7 2.4,1.7, height 1.35
1812_HV [mil] "PRG recommended land pattern"
  rect 60x140 smd: 1(-85,0) 2(85,0)
  silkscreen extent -129,-84 129,84, body extent -94,-67 94,67, height 53
2010 [mm] "Chip Capacitor, Body 5.08x2.54mm, IPC Medium Density"
  rect 1.6x2.7 smd: 1(-2.3,0) 2(2.3,0)
  silkscreen extent -3.42,-1.65 3.42,1.65, body extent -2.73,-1.45 2.73,1.45, height 1.66
2010L [mm]
  rect 1.2x2.7 smd: 1(-2.2,0) 2(2.2,0)
  silkscreen extent -1.2,-1.25 1.2,1.25, body extent -2.73,-1.45 2.73,1.45, height 1.66
CAPSMT_62_F61 [mm] "6.3 x 5.8mm:  Chemi-Con F61"
  rect 3.5x1.6 smd: 1(-2.675,0.025) 2(2.725,0.025)
  silkscreen extent -3.34,-3.38 3.46,3.42, body extent -3.37,-3.38 3.46,3.43, height 6.1
CONN_2510-6002 [mm] "3M 2500 series TS-0770-L December 15, 2011"
  rect 1.65x1.65 hole 1.016 mask+0: 1(-5.08,-1.27)
  round 1.65 hole 1.016 mask+0: 2(-5.08,1.27) 3(-2.54,-1.27) 4(-2.54,1.27) 5(0,-1.27) 6(0,1.27) 7(2.54,-1.27) 8(2.54,1.27) 9(5.08,-1.27) 10(5.08,1.27)
  silkscreen extent -10.01,-4.17 10.01,4.47, body extent -10.01,-4.11 10.01,4.52, height 9.92
CONN_PEC02SAAN [mm] "SULLINS"
  rrect7% 1.5x1.5 hole 1.016: 1(-1.27,0)
  round 1.5 hole 1.016: 2(1.27,0)
  silkscreen extent -2.54,-1.52 2.54,1.27, body extent -2.54,-1.27 2.54,1.27, height 8.38
D0008A-MFG [mm]
  rrect17% 1.55x0.6 smd paste+0 mask+0: 1(-2.7,1.905) 2(-2.7,0.635) 3(-2.7,-0.635) 4(-2.7,-1.905) 5(2.7,-1.905) 6(2.7,-0.635) 7(2.7,0.635) 8(2.7,1.905)
  silkscreen extent -4.17,-2.5 1.5,2.5, body extent -3,-2.45 3,2.45, height 1.75
DBV0005A_L [mm] "SOT23, 5-Leads, Body 2.9x1.6mm, Pitch 0.95mm, Lead Span 2.8mm, IPC High Density"
  rrect18% 0.8x0.55 smd: 1(-1.275,0.95) 2(-1.275,0) 3(-1.275,-0.95) 4(1.275,-0.95) 5(1.275,0.95)
  silkscreen extent -0.35,-1.55 0.35,1.55, body extent -1.42,-1.46 1.42,1.46, height 1.09
DBV0006A_N [mm] "SOT23, 6-Leads, Body 2.9x1.6mm, Pitch 0.95mm, Lead Span 2.8mm, IPC Medium Density"
  rrect17% 1x0.6 smd: 1(-1.375,0.95) 2(-1.375,0) 3(-1.375,-0.95) 4(1.375,-0.95) 5(1.375,0) 6(1.375,0.95)
  silkscreen extent -1.68,-1.55 0.5,1.55, body extent -1.42,-1.46 1.42,1.46, height 1.12
DBZ0003A_N [mm] "SOT23, 3-Leads, Body 2.9x1.3mm, Pitch 0.95mm, Lead Span 2.4mm, IPC Medium Density"
  rrect17% 1x0.6 smd: 1(-1.2,0.95) 2(-1.2,-0.95) 3(1.2,0)
  silkscreen extent 0.2,-1.5 0.7,1.5, body extent -1.26,-1.46 1.26,1.46, height 0.98
DGK0008A_N [mm] "TSOP, 8-Leads, Body 3x3mm, Pitch 0.65mm, IPC Medium Density"
  oval 1.35x0.45 smd: 1(-2.225,0.975) 2(-2.225,0.325) 3(-2.225,-0.325) 4(-2.225,-0.975) 5(2.225,-0.975) 6(2.225,-0.325) 7(2.225,0.325) 8(2.225,0.975)
  silkscreen extent -2.75,-1.55 0.95,1.55, body extent -2.45,-1.5 2.45,1.5, height 0.96
DGS0010A-MFG [mm]
  rrect33% 1.45x0.3 smd paste+0 mask+0: 1(-2.2,1) 2(-2.2,0.5) 3(-2.2,0) 4(-2.2,-0.5) 5(-2.2,-1) 6(2.2,-1) 7(2.2,-0.5) 8(2.2,0) 9(2.2,0.5) 10(2.2,1)
  silkscreen extent -3.6,-1.55 1.05,1.55, body extent -3.03,-1.8 3.03,1.8, height 0.25
DNH0008A_NV [mm] "8 pin VSONP, 0.65 mm pitch"
  rrect50% 0.7x0.4 smd paste-0.05 mask-0.05: 1(-1.55,0.975) 2(-1.55,0.325) 3(-1.55,-0.325) 4(-1.55,-0.975) 5(1.55,-0.975) 6(1.55,-0.325) 7(1.55,0.325) 8(1.55,0.975)
  rrect14% 0.705x1.125 on Top Paste: 9(-0.208,0.662) 9(-0.208,-0.663) 9(0.697,-0.663) 9(0.697,0.662)
  rrect6% 1.775x2.45 on Top Solder: 9(0.327,0)
  rrect4% 2.51x2.55 smd paste-1.5 mask-1.5: 9(0.645,0)
  rect 0.5x0.3 on Top Solder: 9(1.175,-0.975) 9(1.175,-0.325) 9(1.175,0.325) 9(1.175,0.975)
  silkscreen extent -1.62,-1.7 1.62,1.7, body extent -1.65,-1.65 1.65,1.66, height 0.91
DQJ0008A [mm] "SMD, 8-Leads, Body 5.75x4.9mm"
  rrect39% 0.91x0.51 smd paste-0.05 mask-0.05: 1(-2.795,1.905) 2(-2.795,0.635) 3(-2.795,-0.635) 4(-2.795,-1.905) 5(2.795,-1.905) 6(2.795,-0.635) 7(2.795,0.635) 8(2.795,1.905)
  rrect8% 1.58x1.25 on Top Paste: 9(-0.38,-1.45) 9(-0.38,0) 9(-0.38,1.45) 9(1.4,-1.45) 9(1.4,0) 9(1.4,1.45)
  rrect3% 3.48x4.47 on Top Solder: 9(0.55,0)
  rrect2% 4.49x4.57 smd paste-2.5 mask-2.5: 9(1.005,0)
  silkscreen extent -3,-2.6 3,2.6, body extent -3.13,-2.45 3.13,2.45, height 1.15
FCC_disclaimer [mil]
Fiducial10-20 [mm]
  round 1 smd mask+0.5: 1(0,0)
  Top Layer 1 keep-out circle w1.178: c0,0 r0.5
FP-BSS123-7-F_SOT23-MFG [mm]
  rrect13% 0.9x0.8 smd paste+0 mask+0: 1(-1,0.95) 2(-1,-0.95) 3(1,0)
  body extent -1.55,-1.6 1.55,1.6, height 0.25
FP-LDT8618-50_SMT_XFRFMR_21MM5_21MM1-MFG [mm]
  rrect8% 1.3x3.5 smd paste+0 mask+0: 1(-7.5,-13.45) 2(-4.5,-13.45) 3(-1.5,-13.45) 4(1.5,-13.45) 5(4.5,-13.45) 6(7.5,-13.45) 7(7.5,13.45) 8(4.5,13.45) 9(1.5,13.45) 10(-1.5,13.45) 11(-4.5,13.45) 12(-7.5,13.45)
  silkscreen extent -10.68,-15.9 10.68,10.87, body extent -10.78,-15.3 10.78,15.3, height 0.25
HLMP-Q150_Red [mm] "SMD, 2-Leads, Body 2.08x2.21mm"
  rect 0.89x0.89 smd: 1(-1.8,0) 2(1.78,0)
  silkscreen extent -3.1,-1.2 2.29,1.2, body extent -1.91,-1.1 1.91,1.1, height 2.82
LPS5030 [mm] "Coilcraft recommended land pattern.  Document 581-2, rev 10/06/08"
  rect 0.75x3.4 smd: 1(-2.125,0) 2(2.125,0)
  rect 1.131x0.92 smd rot 135: 1(-1.776,-1.776) 2(1.776,1.776)
  rect 1.131x0.92 smd rot 45: 1(-1.776,1.776) 2(1.776,-1.776)
  rect 0.95x0.8 smd: 1(-1.225,2.1) 1(-1.225,-2.1) 2(1.225,2.1) 2(1.225,-2.1)
  silkscreen extent -3.45,-2.8 2.8,2.8, body extent -2.5,-2.5 2.5,2.5, height 3.02
MLP08S [mm] "Fairchild MLP08S recommended land pattern"
  rect 0.7x0.42 smd mask+0.051: 1(-1.4,0.975) 2(-1.4,0.325) 3(-1.4,-0.325) 4(-1.4,-0.975) 5(1.4,-0.975) 6(1.4,-0.325) 7(1.4,0.325) 8(1.4,0.975)
  Top Layer 1 region: -0.4,-1.185 1.3,-1.185 1.3,1.185 -0.4,1.185
  silkscreen extent -1.8,-1.8 1.8,1.8, body extent -1.67,-1.67 1.67,1.67, height 0.81
N04C [mm] "FAIRCHILD"
  rect 1.3x1.5 smd mask+0.065: 1(-4.587,1.27) 2(-4.612,-1.27) 3(4.588,-1.27) 4(4.613,1.27)
  silkscreen extent -3.56,-2.3 3.56,2.72, body extent -5.08,-2.3 5.08,2.3, height 3.87
On-Shore_ED120_2DS [mm] "ONSHORE"
  rrect5% 2x2 hole 1.25: 1(-2.54,0)
  round 2 hole 1.25: 2(2.54,0)
  silkscreen extent -5.6,-4 5.12,5, body extent -5.78,-4 5.08,5, height 13
POWERDI5 [mm] "Diodes Inc recommended land pattern, ap02001.pdf rev 60"
  rect 1.4x1.39 smd: 1(-1.991,0.92) 2(-1.991,-0.92)
  rect 4.86x3.36 smd: 3(1.991,0)
  silkscreen extent -1.7,-2.1 3.8,2.1, body extent -2.27,-2.03 4.33,2.03, height 1.17
RGW0020B [mm] "QFN, 20-Leads, Body 5x5mm, Pitch 0.65mm, Thermal Pad 2.2x2.2mm, TI Recommended"
  rrect32% 0.75x0.31 smd: 1(-2.325,1.3) 2(-2.325,0.65) 3(-2.325,0) 4(-2.325,-0.65) 5(-2.325,-1.3) 11(2.325,-1.3) 12(2.325,-0.65) 13(2.325,0) 14(2.325,0.65) 15(2.325,1.3)
  rrect32% 0.31x0.75 smd: 6(-1.3,-2.325) 7(-0.65,-2.325) 8(0,-2.325) 9(0.65,-2.325) 10(1.3,-2.325) 16(1.3,2.325) 17(0.65,2.325) 18(0,2.325) 19(-0.65,2.325) 20(-1.3,2.325)
  rrect10% 0.98x0.98 on Top Paste: 21(-0.59,-0.59) 21(-0.59,0.59) 21(0.59,-0.59) 21(0.59,0.59)
  rrect5% 2.2x2.2 smd paste-1.1: 21(0,0)
  silkscreen extent -2.73,-2.73 2.73,2.73, body extent -2.5,-2.5 2.5,2.5, height 0.97
RMT0045A-MFG [mm]
  rrect50% 0.6x0.2 smd paste+0 mask+0: 1(-2.4,2.6) 2(-2.4,2.2) 3(-2.4,1.8) 4(-2.4,1.4) 5(-2.4,1) 6(-2.4,0.6) 7(-2.4,0.2) 8(-2.4,-0.2) 9(-2.4,-0.6) 10(-2.4,-1.4) 11(-2.4,-1.8) 12(-2.4,-2.2) 13(-2.4,-2.6) 23(2.4,-2.6) 24(2.4,-2.2) 25(2.4,-1.8) 26(2.4,-1.4) 27(2.4,-1) 28(2.4,-0.6) 29(2.4,-0.2) 30(2.4,0.6) 31(2.4,1) 32(2.4,1.4) 33(2.4,1.8) 34(2.4,2.2) 35(2.4,2.6)
  rrect50% 0.2x0.6 smd paste+0 mask+0: 14(-1.8,-3.4) 15(-1.4,-3.4) 16(-1,-3.4) 17(-0.6,-3.4) 18(-0.2,-3.4) 19(0.2,-3.4) 20(0.6,-3.4) 21(1,-3.4) 22(1.4,-3.4) 36(1.8,3.4) 37(1.4,3.4) 38(1,3.4) 39(0.6,3.4) 40(0.2,3.4) 41(-0.2,3.4) 42(-0.6,3.4) 43(-1,3.4) 44(-1.4,3.4) 45(-1.8,3.4)
  rrect5% 3.7x2.1 smd paste-1000 mask+0: 46(0,1.4)
  rrect5% 2.9x2.15 smd paste-1000 mask+0: 47(0,-1.375)
  silkscreen extent -3.37,-3.55 2.55,3.55, body extent -2.8,-3.8 2.8,3.8, height 0.25
Samtec_HTSW-105-07-G-S [mm] "Samtec 100mil, 1x5, 230 mil above insulator"
  rrect6% 1.65x1.65 hole 1.016: 1(-5.08,0)
  round 1.65 hole 1.016: 2(-2.54,0) 3(0,0) 4(2.54,0) 5(5.08,0)
  silkscreen extent -7.11,-1.27 6.35,1.27, body extent -6.35,-1.27 6.35,1.27, height 8.38
Samtec_TSW-103-08-x-S [mm] "Header, 2.54mm, 3x1, TH"
  rrect50% 1.53x1.53 hole 1.02: 1(-2.54,0)
  round 1.53 hole 1.02: 2(0,0) 3(2.54,0)
  body extent -3.94,-1.27 3.81,1.27, height 8.38
SM_RADIAL_8MM [mm] "Nichicon 8x10"
  rect 3.5x2.5 smd: 1(-3.25,0) 2(3.25,0)
  silkscreen extent -4.25,-4.25 4.25,4.25, body extent -4.25,-4.25 4.25,4.25, height 10.5
SM_RADIAL_10BMM [mm] "Nichicon 10x10"
  rect 4x2.5 smd: 1(-4,0) 2(4,0)
  silkscreen extent -5.25,-5.25 5.25,5.25, body extent -5.25,-5.25 5.25,5.25, height 10.5
SMB [mil] "Molded Diode, 2-Leads, Body 5.4x3.6mm, IPC Medium Density, based on OnSemi component dimensions"
  rect 85x107.99 smd: 1(-87.01,0) 2(87.01,0)
  silkscreen extent -155,-82 125,82, body extent -106,-71 106,71, height 91
SOD-123 [mm] "On Semi recommended land pattern"
  rect 0.915x1.22 smd: 1(-1.637,0) 2(1.637,0)
  silkscreen extent -2.74,-1.17 2.03,1.17, body extent -1.93,-0.9 1.93,0.9, height 1.35
SOD-323F [mm] "NXP recommended land pattern"
  rect 0.6x0.6 smd paste-0.05: 1(-1.1,0) 2(1.1,0)
  silkscreen extent -2.06,-0.86 1.53,0.86, body extent -1.35,-0.67 1.35,0.68, height 0.79
SOD-523 [mm] "NXP Semiconductor recommended land pattern, nominal STEP model"
  rect 0.8x0.6 smd paste-0.05: 1(-0.55,0) 2(0.55,0)
  silkscreen extent -1.65,-0.66 1.2,0.66, body extent -0.8,-0.4 0.8,0.4, height 0.72
SOP-4 [mm] "Vishay Half Pitch Mini-Flat Package"
  rect 1.3x0.9 smd: 1(-3.15,0.635) 2(-3.15,-0.635) 3(3.15,-0.635) 4(3.15,0.635)
  silkscreen extent -2.2,-1.41 2.2,1.39, body extent -3.5,-1.4 3.5,1.4, height 2.12
SOT-23L [mm] "SOT23, 3-Leads, Body 2.9x1.3mm, Pitch 0.95mm, Lead Span 2.5mm, IPC High Density"
  rrect50% 0.8x0.6 smd: 1(-1.1,0.95) 2(-1.1,-0.95) 3(1.1,0)
  silkscreen extent -1.5,-1.5 0.7,1.5, body extent -1.16,-1.45 1.21,1.45, height 1
SOT-89-3 [mm] "SOT, 3-Leads, Body 4.6 x 2.6 mm, Pitch 1.5mm"
  rect 1.4x0.9 smd: 1(-1.9,1.5) 3(-1.9,-1.5)
  rect 1.8x0.9 smd: 2(-1.7,0)
  oct 3.4x1.9 smd: 4(0.9,0)
  silkscreen extent -1.3,-2.45 1.33,2.45, body extent -2.42,-2.28 1.83,2.32, height 1.62
TEC_1-406541-1 [mm] "TE Connectivity"
  round 1.4 hole 0.89: 1(3.56,-0.18) 2(2.54,1.6) 3(1.52,-0.18) 4(0.5,1.6) 5(-0.52,-0.18) 6(-1.54,1.6) 7(-2.56,-0.18) 8(-3.58,1.6)
  round 2.1 hole 1.57: 9(8.12,0.71) 10(-8.14,0.71)
  round 3.759 hole 3.251: 11(6.34,-2.72) 12(-6.36,-2.72)
  silkscreen extent -9.69,-8 9.69,8.06, body extent -9.33,-8 9.31,7.75, height 14.8
TERM_BLK_ED555-2DS [mil]
  rrect4% 100x100 hole 50: 1(0,0)
  round 100 hole 50: 2(138,0)
  silkscreen extent -93,-161 215,113, body extent -69,-150 207,106, height 323
TRANS_Fairchild_PQFN08A [mm] "Fairchild PQFN08A recommended land pattern"
  rect 1.27x0.61 smd: 1(-2.67,1.905) 2(-2.67,0.635) 3(-2.67,-0.635) 4(-2.67,-1.905) 5(2.67,-1.905) 6(2.67,-0.635) 7(2.67,0.635) 8(2.67,1.905)
  Top Layer 1 region: -1.215,-2.55 2.535,-2.55 2.535,2.55 -1.215,2.55
  silkscreen extent -3.2,-2.7 3.2,2.7, body extent -3.05,-2.55 3.05,2.55, height 1.11
TSW-103-07-G-S [mm] "Samtec 100mil, 1x3, 230 mil above insulator"
  rrect50% 1.65x1.65 hole 1.016: 1(-2.54,0)
  round 1.65 hole 1.016: 2(0,0) 3(2.54,0)
  body extent -3.81,-1.27 3.81,1.27, height 8.38
WEEE_Minimum [mil] "WEEElie bin"
  silkscreen extent -95,-172 99,104
Wurth_7490220122 [mm] "SMD, 24-Leads, Body 14.7x18.29mm"
  rect 2.29x0.76 smd: 1(-7.24,6.985) 2(-7.24,5.715) 3(-7.24,4.445) 4(-7.24,3.175) 5(-7.24,1.905) 6(-7.24,0.635) 7(-7.24,-0.635) 8(-7.24,-1.905) 9(-7.24,-3.175) 10(-7.24,-4.445) 11(-7.24,-5.715) 12(-7.24,-6.985) 13(7.24,-6.985) 14(7.24,-5.715) 15(7.24,-4.445) 16(7.24,-3.175) 17(7.24,-1.905) 18(7.24,-0.635) 19(7.24,0.635) 20(7.24,1.905) 21(7.24,3.175) 22(7.24,4.445) 23(7.24,5.715) 24(7.24,6.985)
  silkscreen extent -7.7,-9.15 7.35,9.15, body extent -7.35,-9.15 7.35,9.15, height 8.81
XAL1010 [mm] "COILCRAFT"
  rect 2.38x11.31 smd: 1(-3.325,0) 2(3.325,0)
  silkscreen extent -5.3,-6 5.3,6, body extent -5.25,-5.9 5.25,5.9, height 10
XAL5030 [mil] "Coilcraft XAL5030 12/12/11"
  rect 46x183 smd: 1(-65,0) 2(65,0)
  silkscreen extent -108,-112 108,112, body extent -108,-112 108,112, height 122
